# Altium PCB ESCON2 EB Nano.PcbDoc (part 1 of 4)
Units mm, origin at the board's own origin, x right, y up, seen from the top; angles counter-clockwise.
Board outline 67 x 70 mm, 6 copper layers (Top Side, Mid Layer 1, Mid Layer 2, Mid Layer 5, Mid Layer 6, Bottom Side), stack 1.48 mm thick; 293 components, 114 nets, 848 pads, 2005 vias.
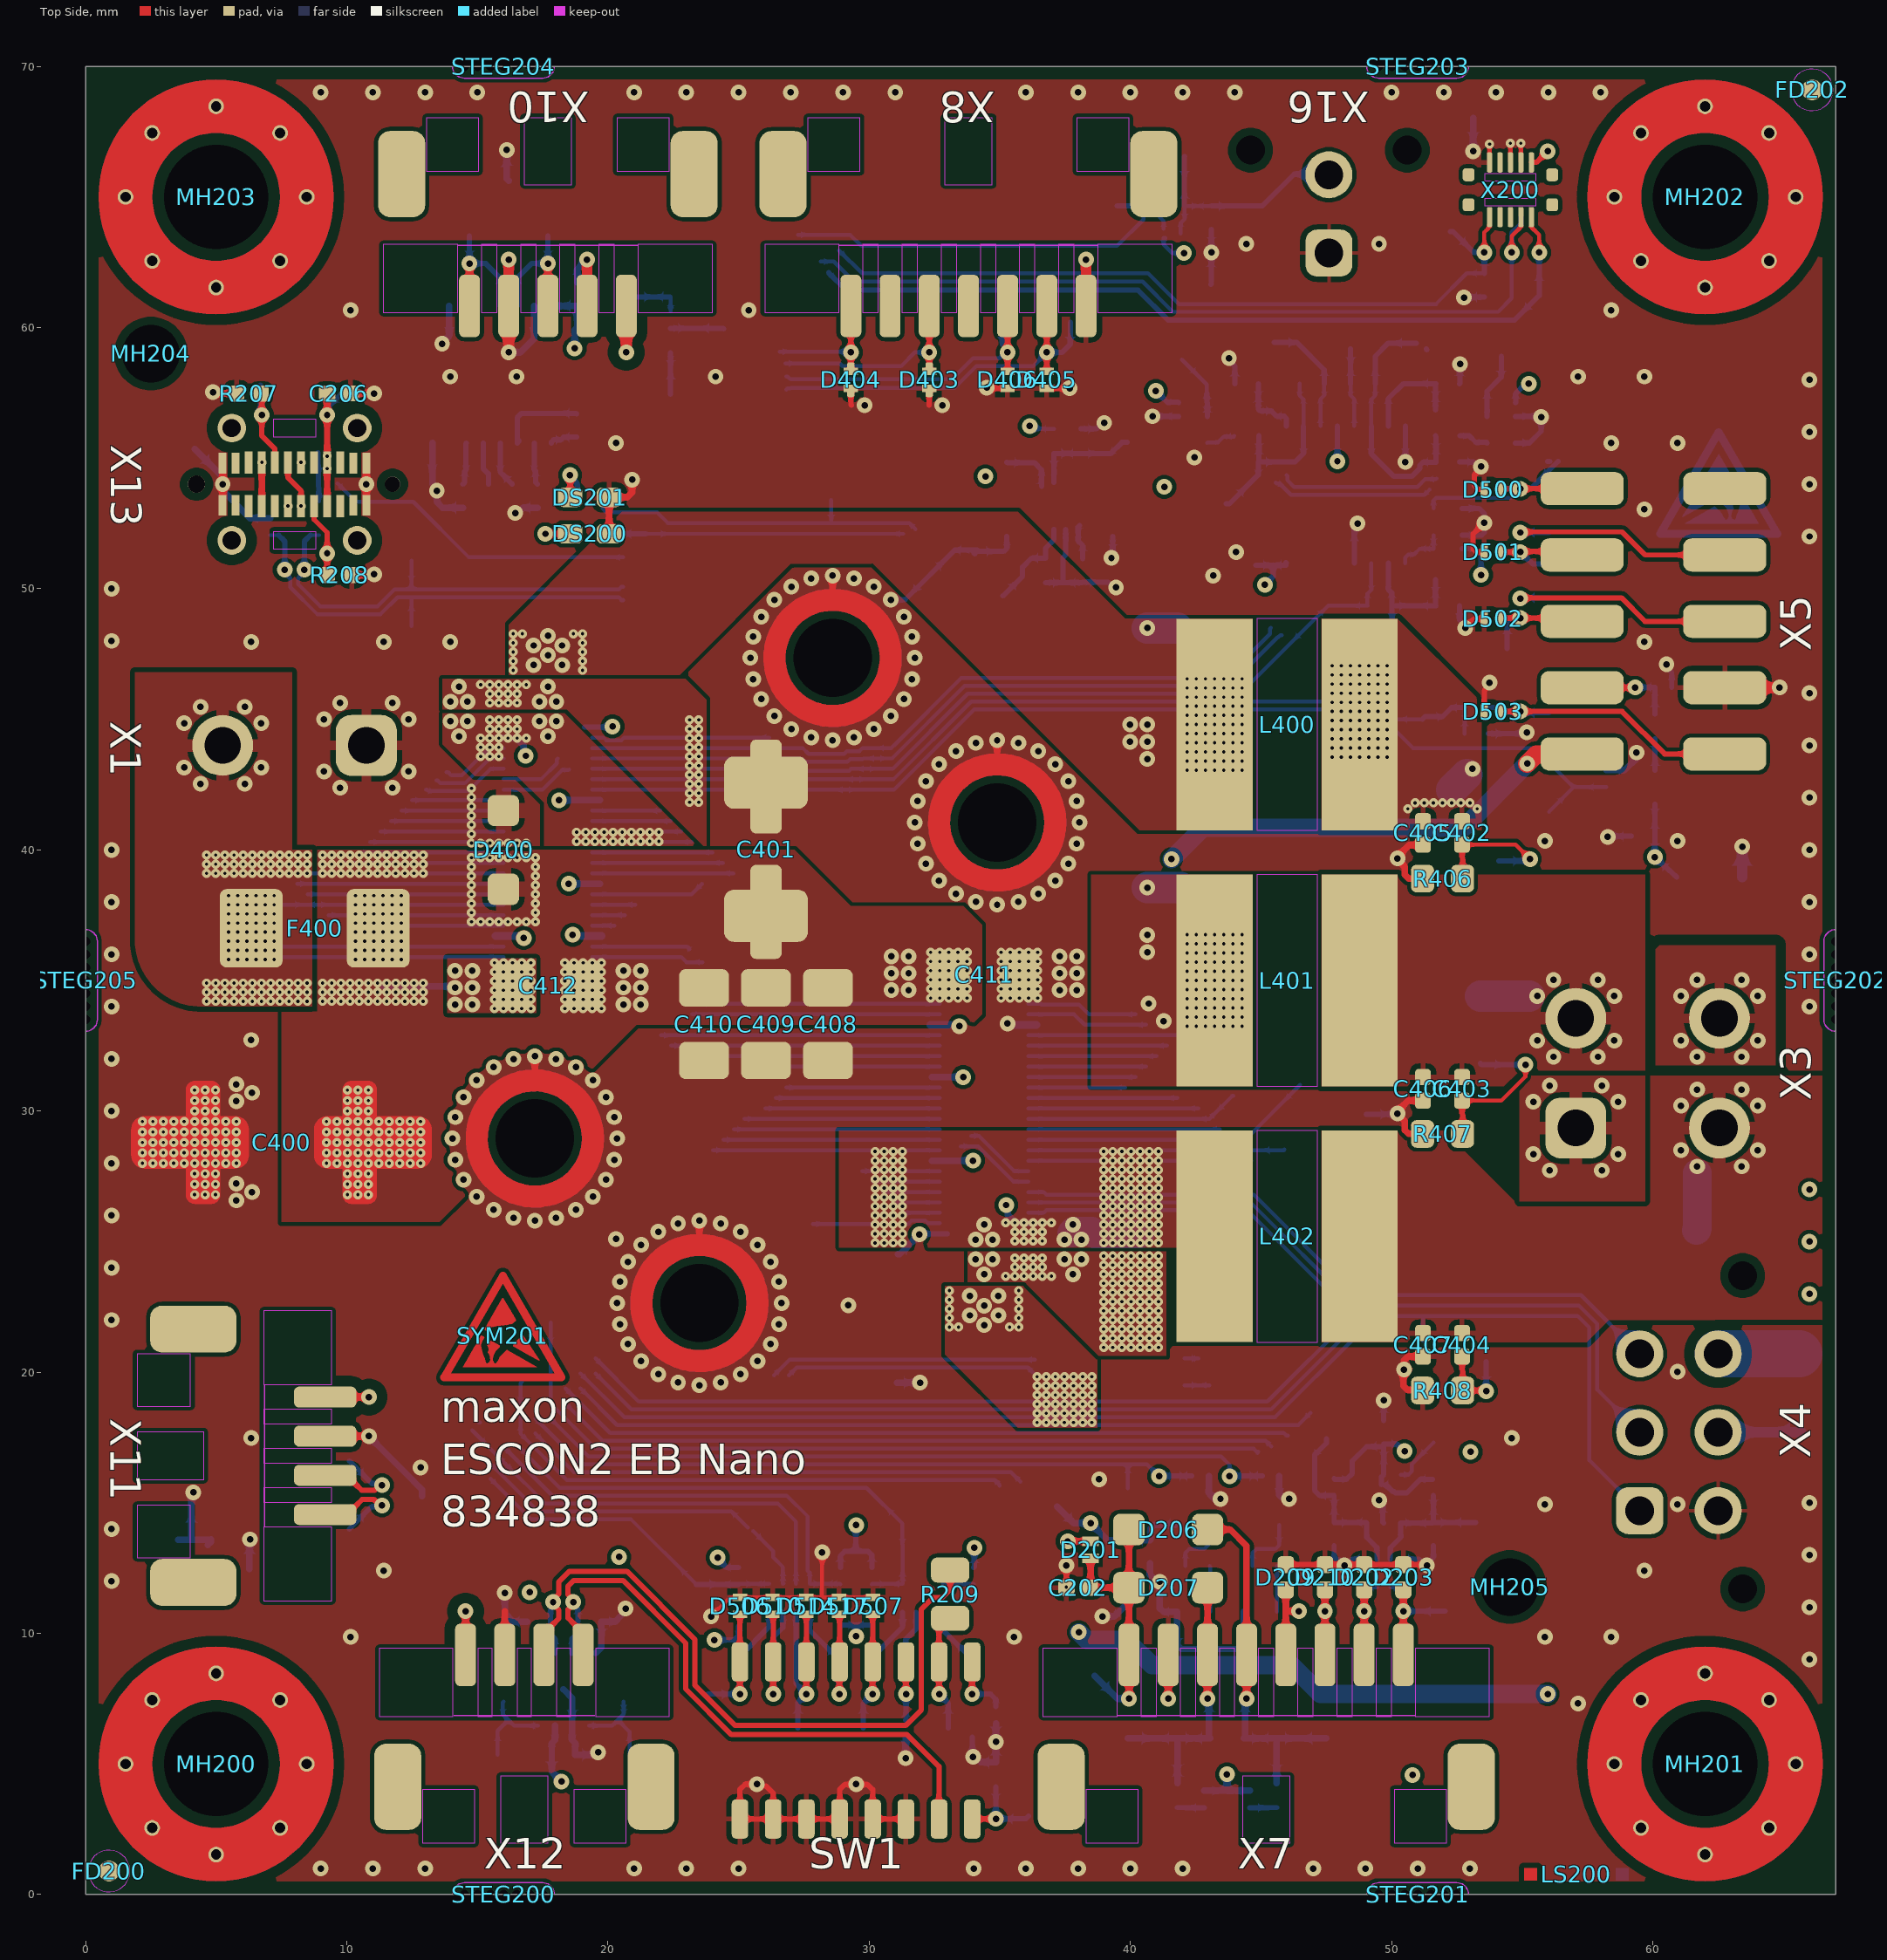
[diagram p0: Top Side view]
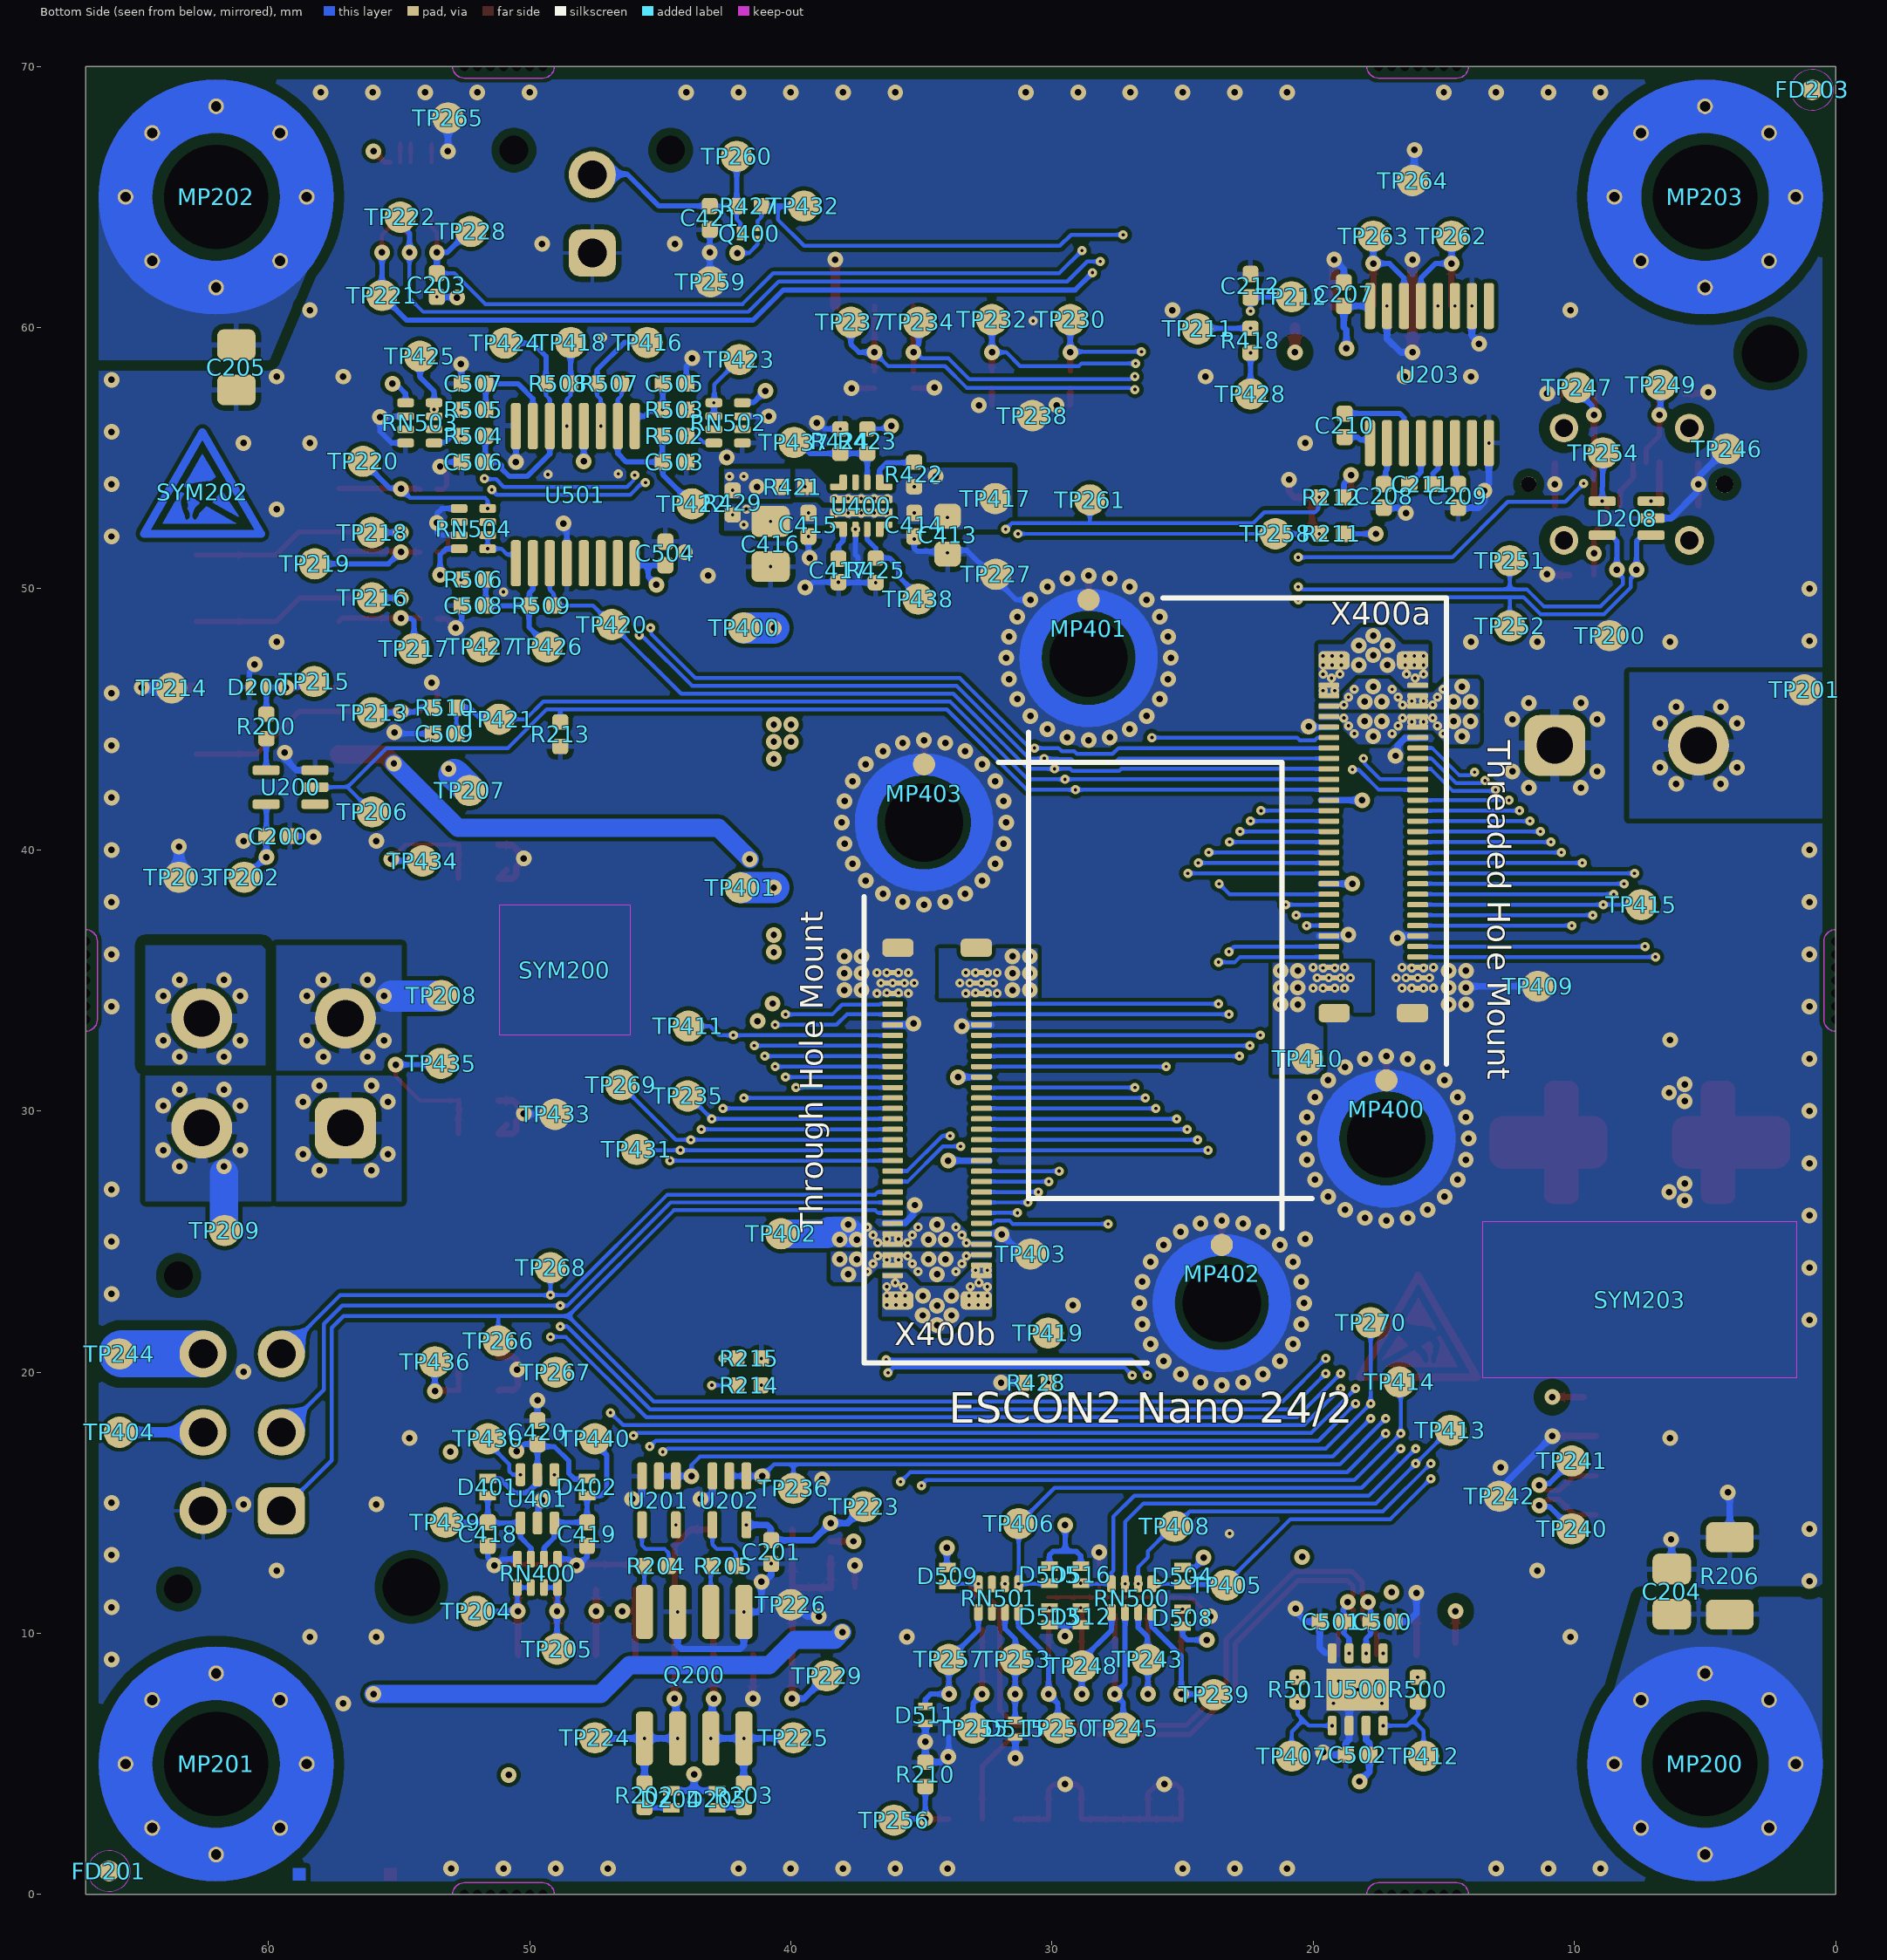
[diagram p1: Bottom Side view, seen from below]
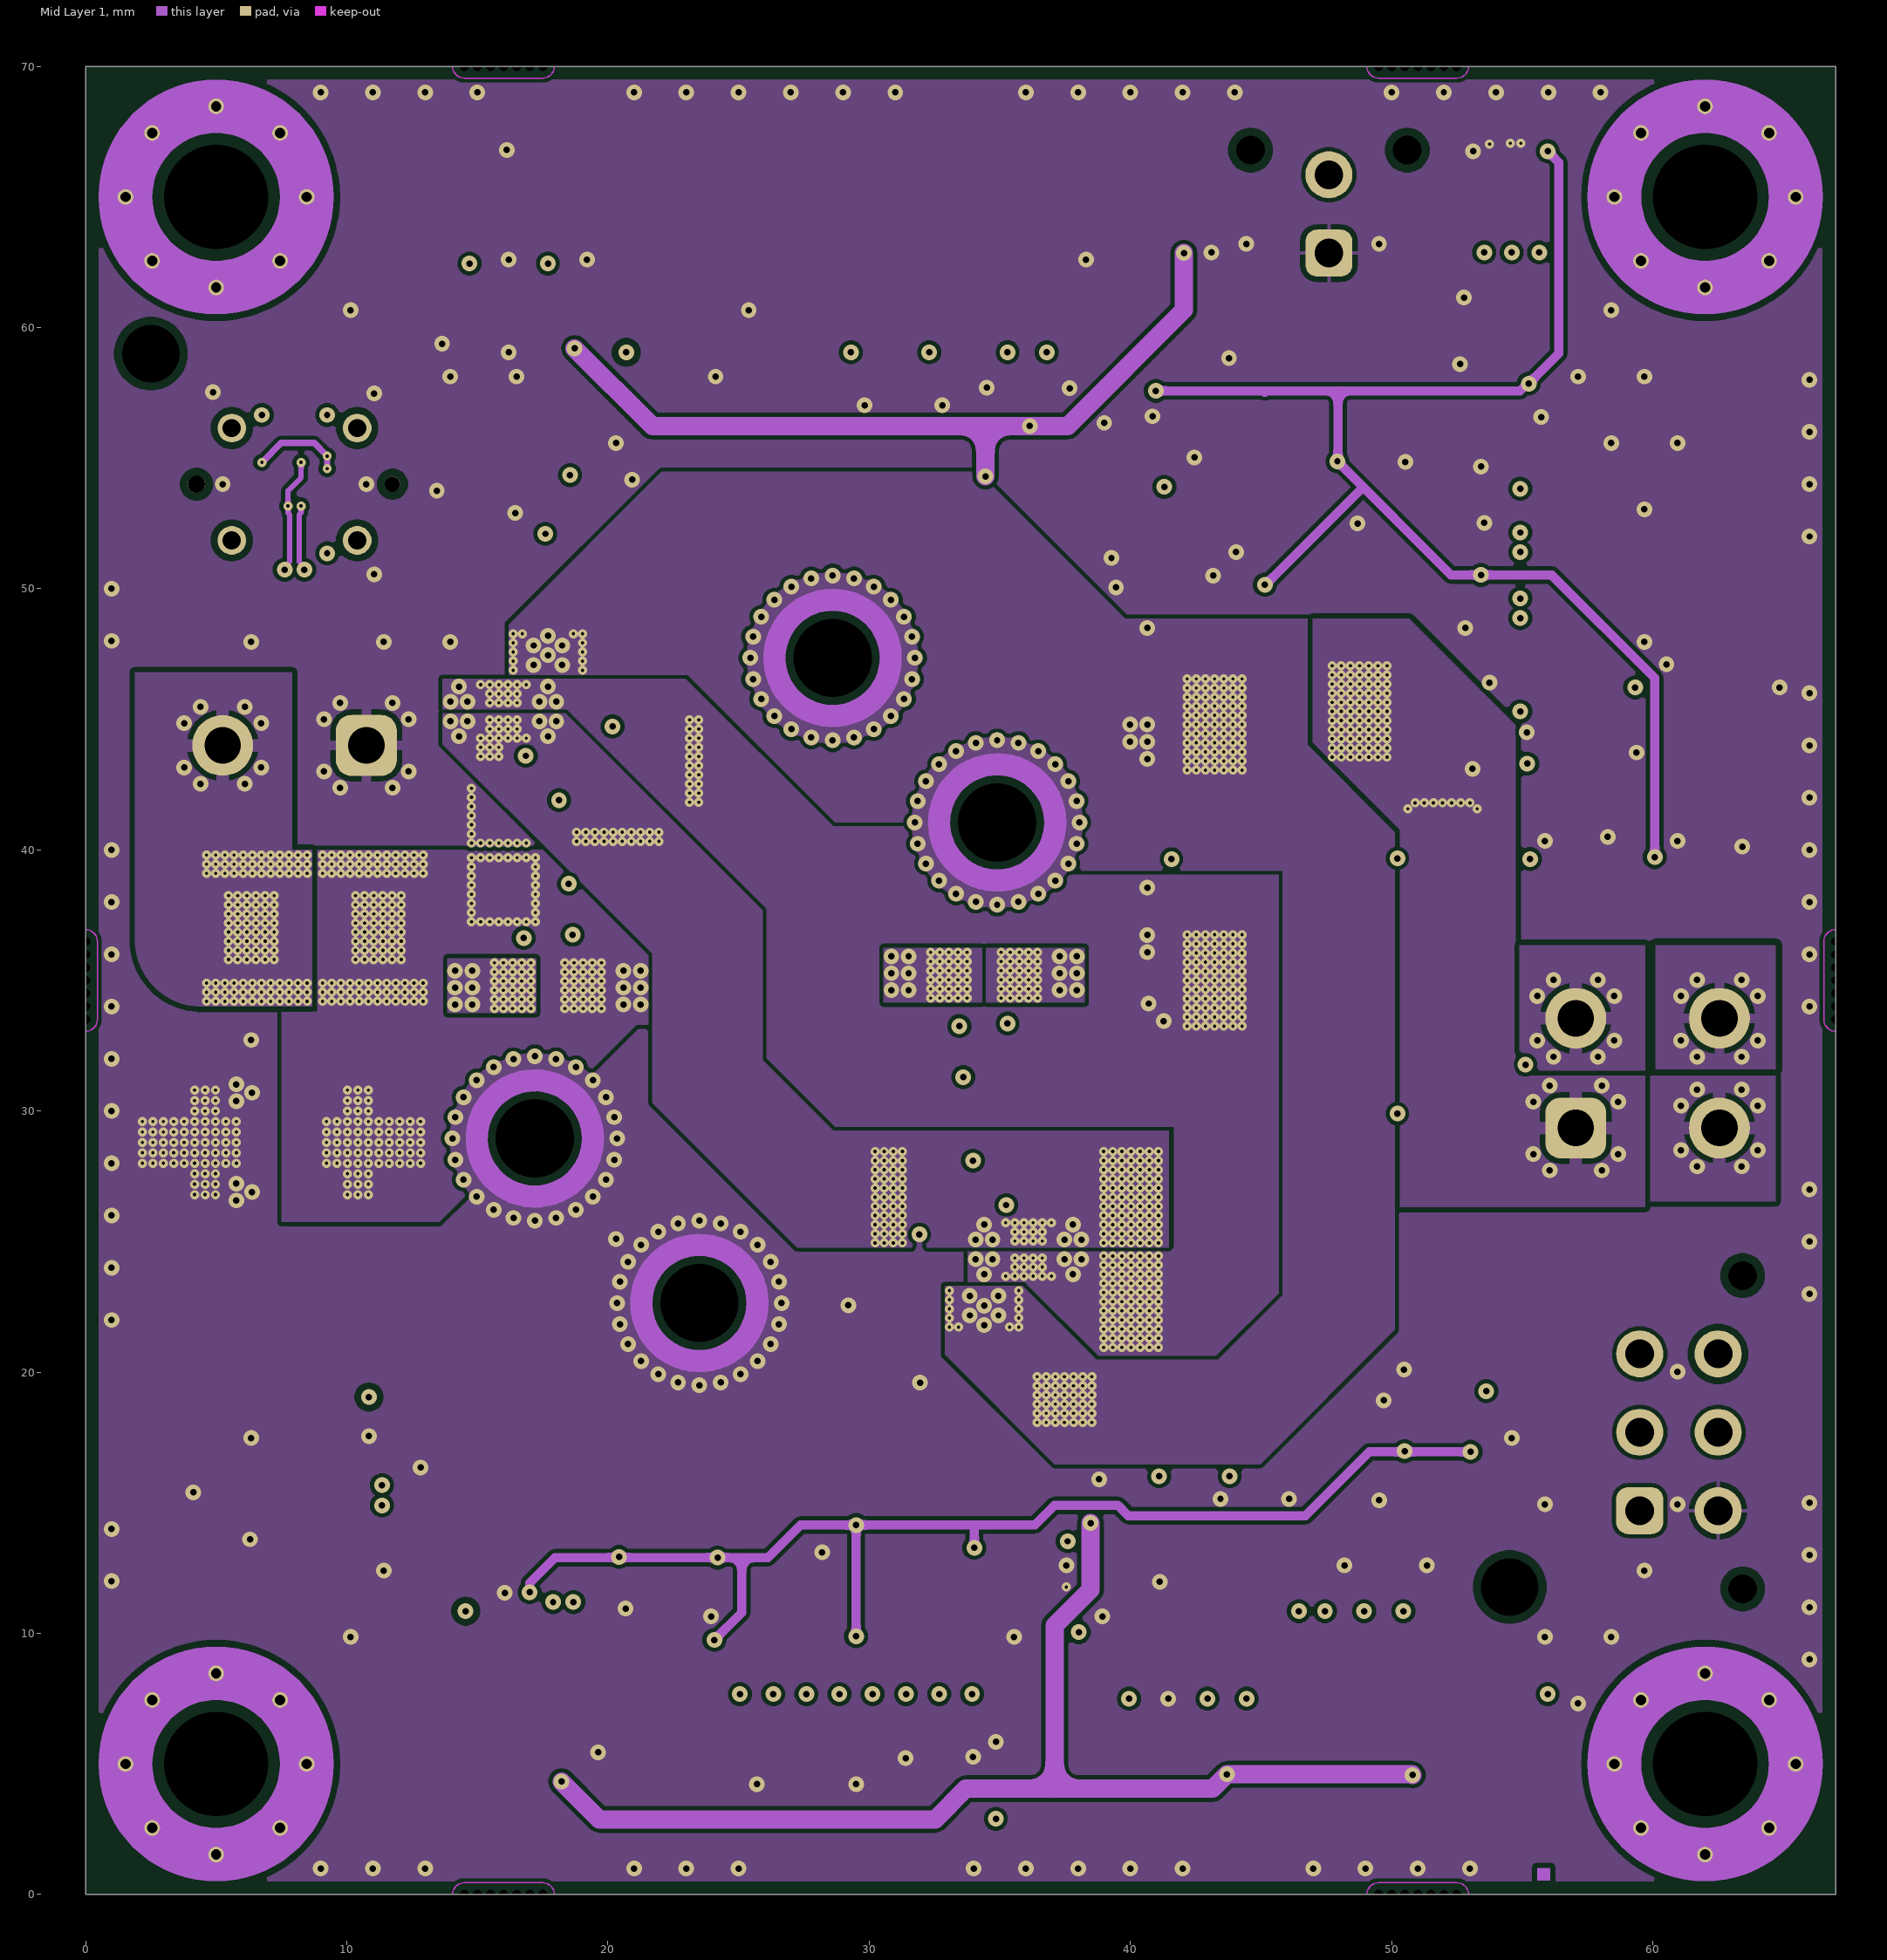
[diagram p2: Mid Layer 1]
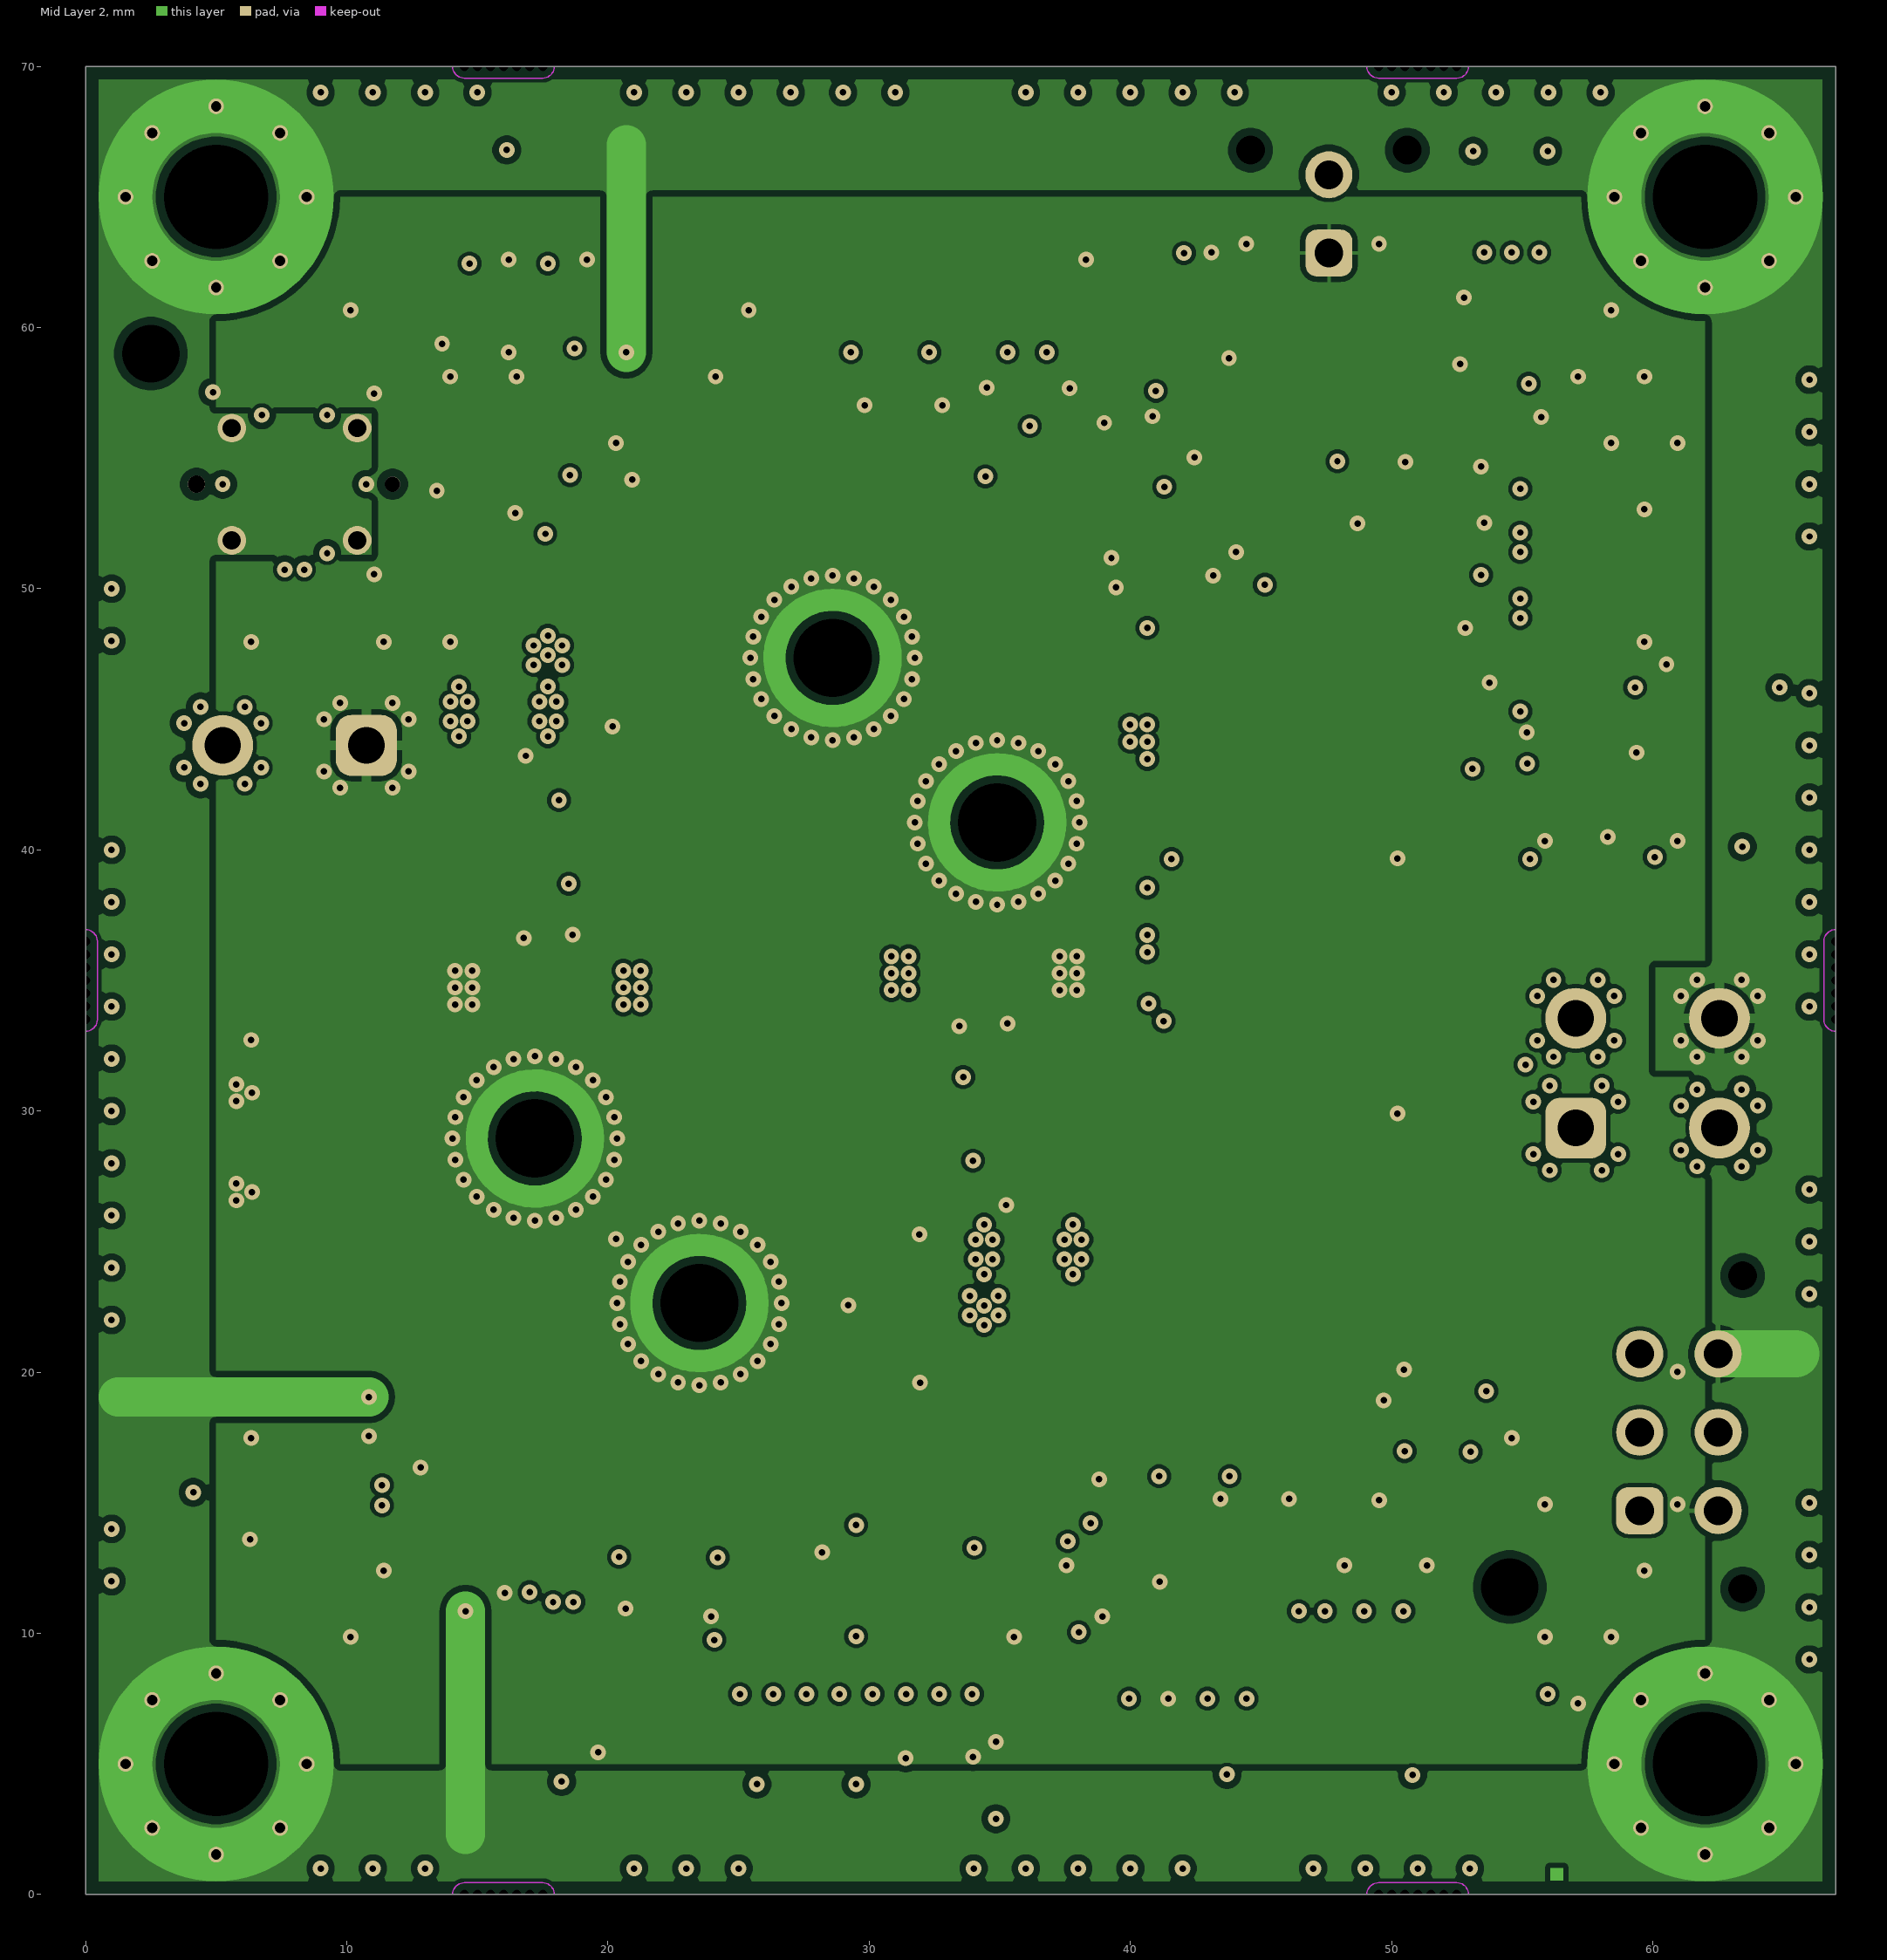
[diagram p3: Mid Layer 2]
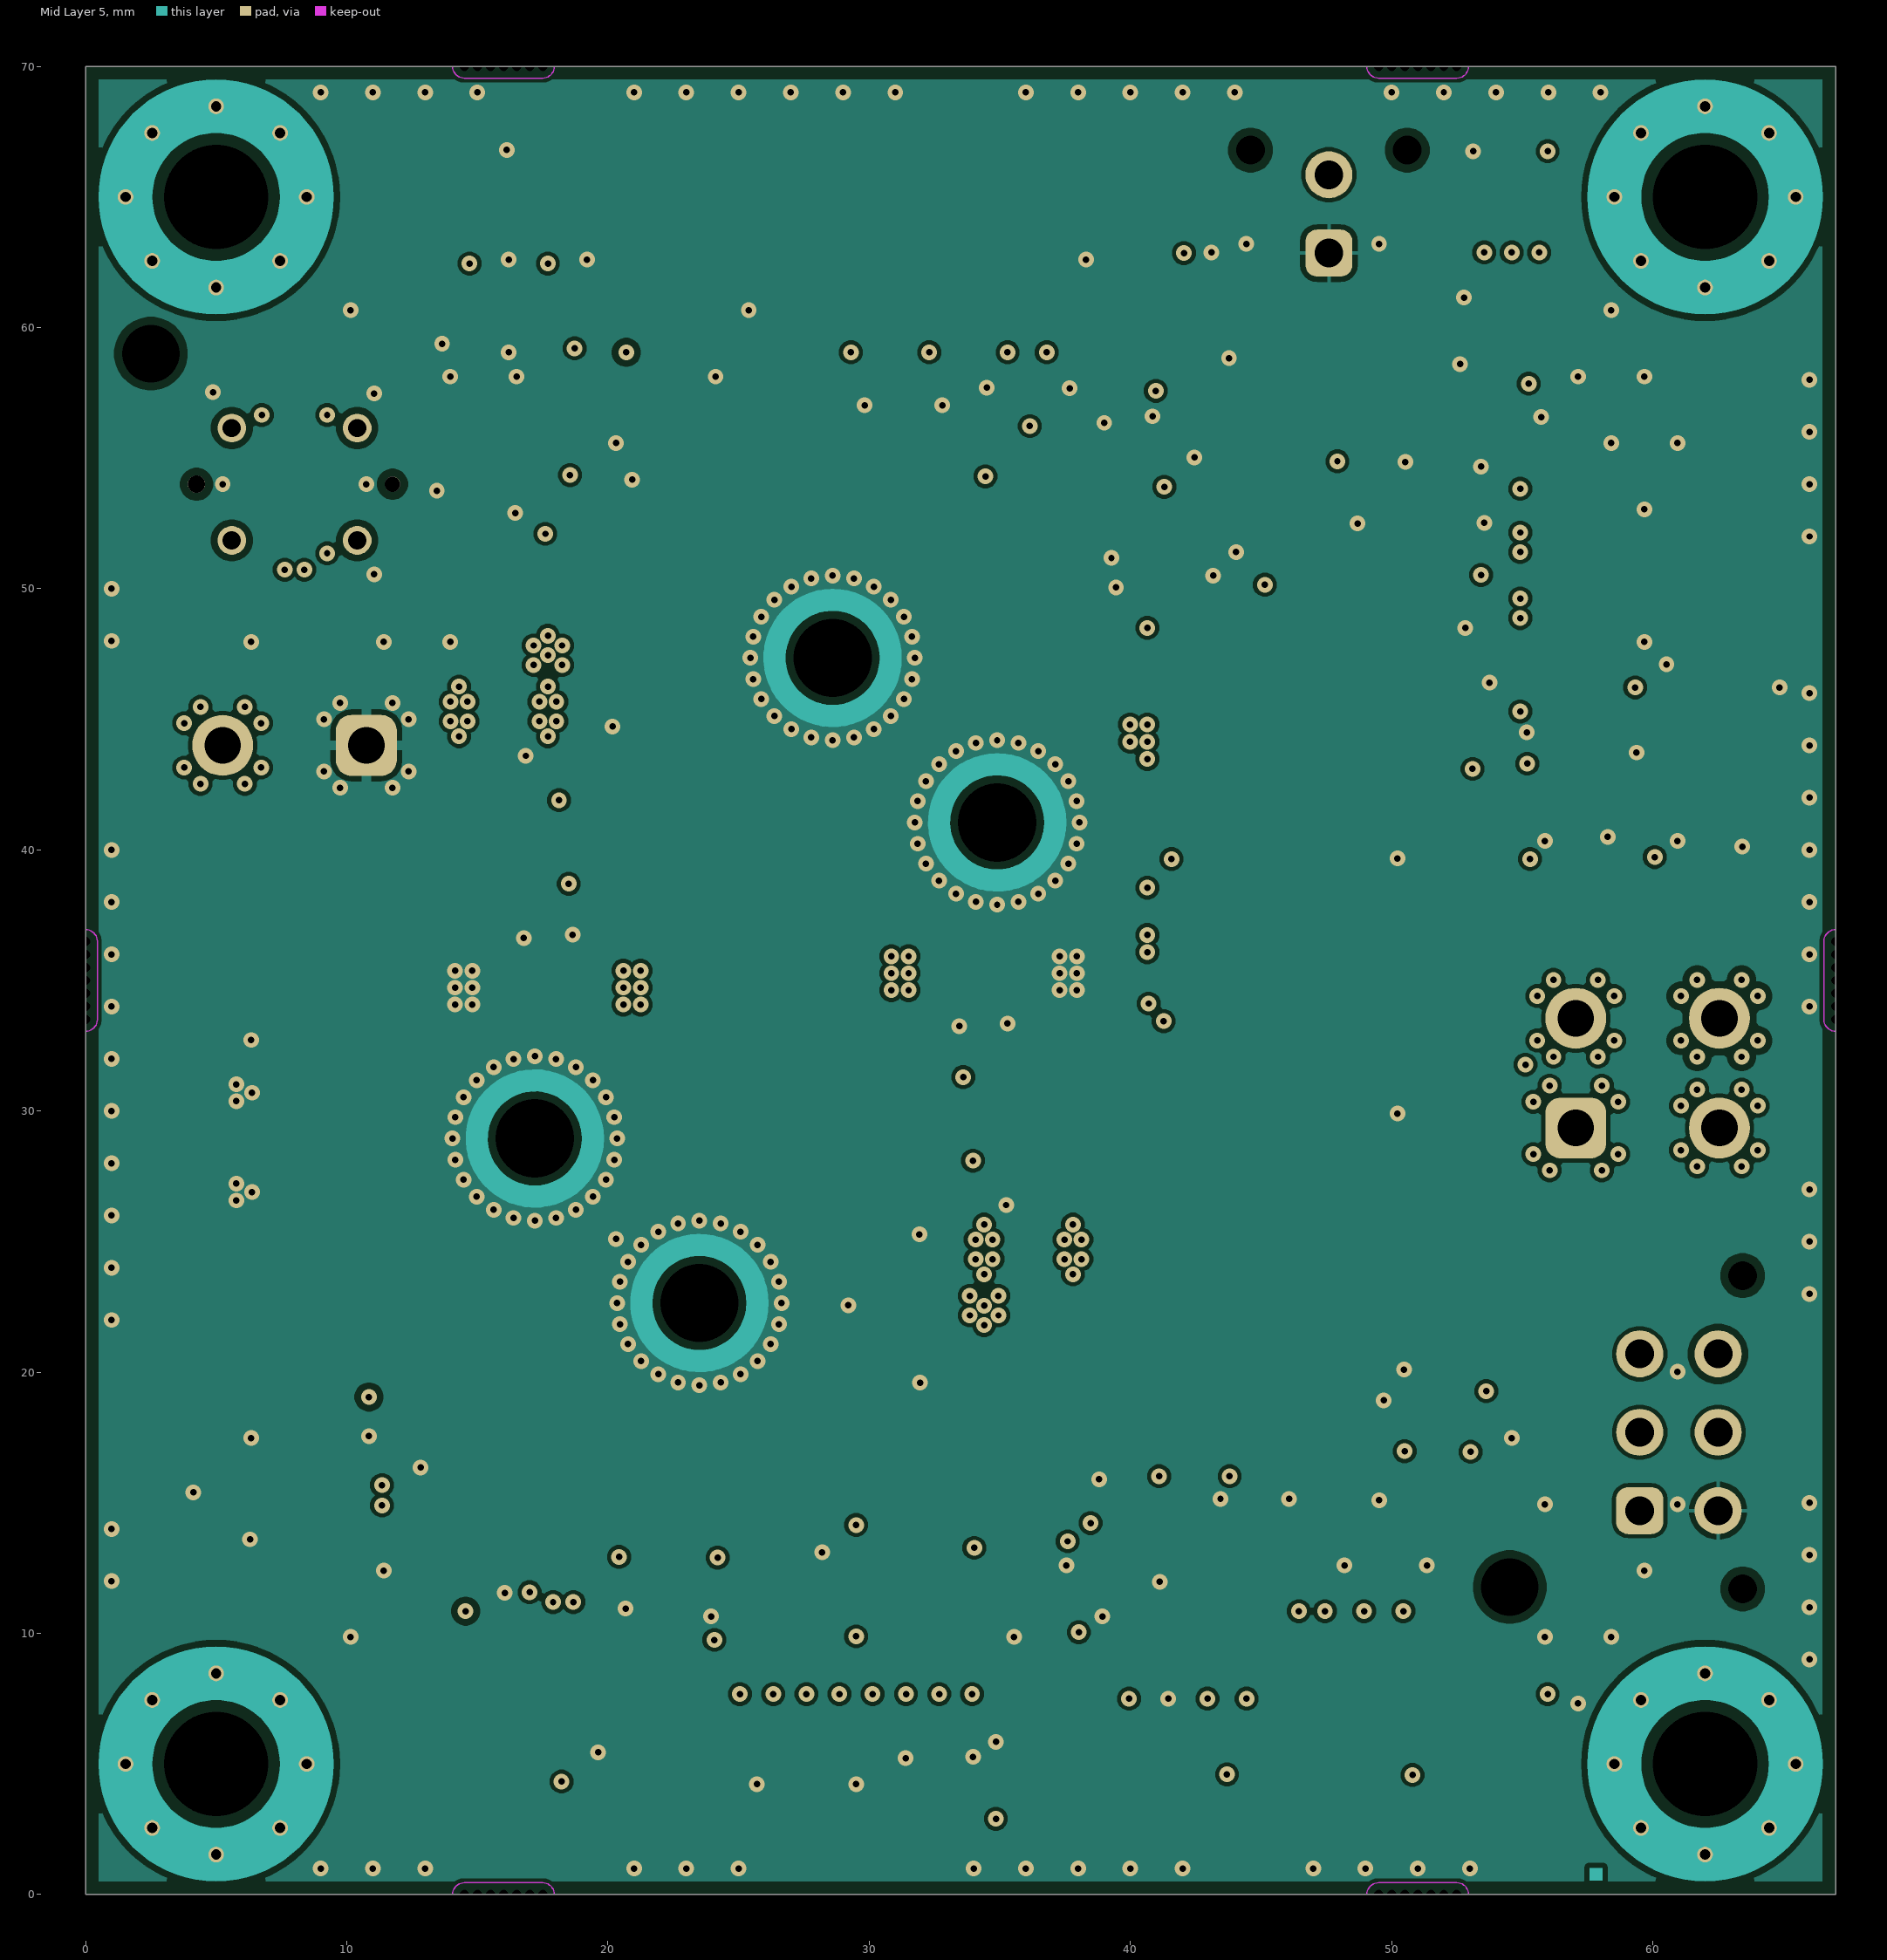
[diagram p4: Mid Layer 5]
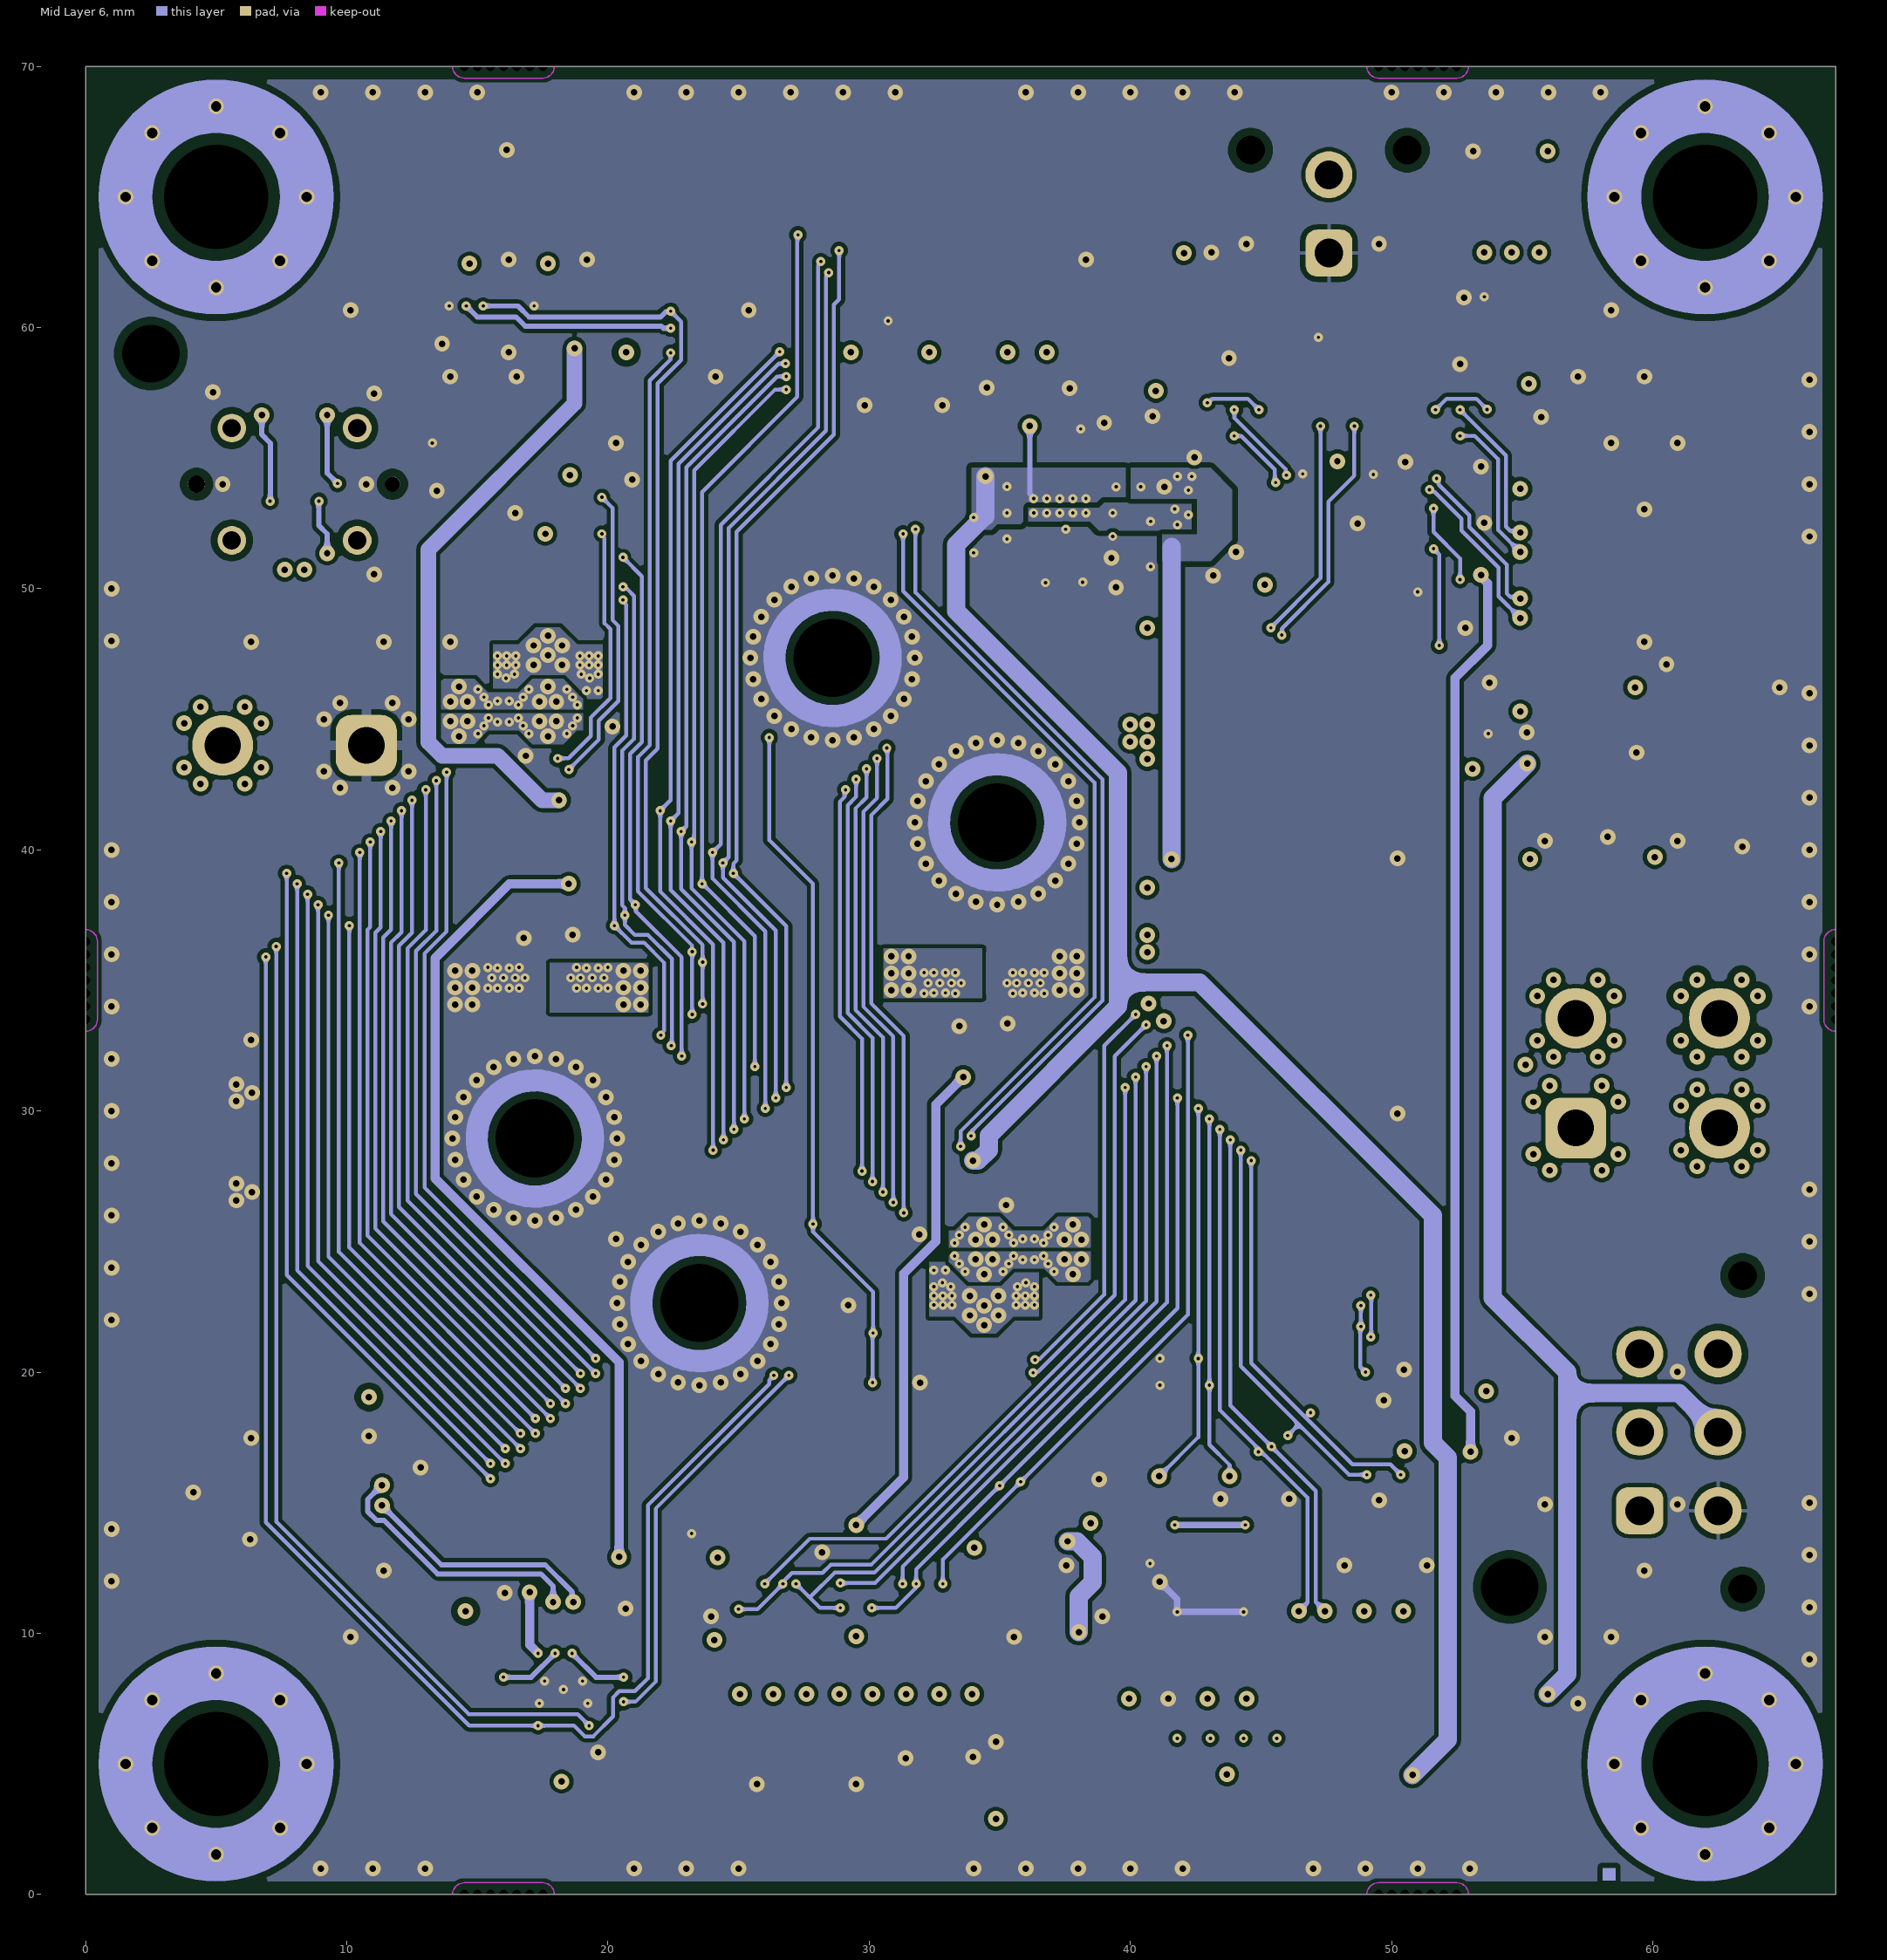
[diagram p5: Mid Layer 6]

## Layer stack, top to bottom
Top Solder: solder mask 0.015, Dk 3.5
Top Side: signal copper 0.03
Dielectric 1: prepreg 0.065, Dk 3.5
Mid Layer 1: signal copper 0.035
Core 1: core 0.51, Dk 5.1
Mid Layer 2: signal copper 0.035
Dielectric 2: prepreg 0.125, Dk 3.7
Mid Layer 5: signal copper 0.035
Core 3: core 0.51, Dk 5.1
Mid Layer 6: signal copper 0.035
Dielectric 4: prepreg 0.065, Dk 3.5
Bottom Side: signal copper 0.035
Bottom Solder: solder mask 0.015, Dk 3.5

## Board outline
0,0 0,70 67,70 67,0

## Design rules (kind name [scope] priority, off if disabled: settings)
AssemblyTestPointUsage [All] p1: valid=2
AssemblyTestpoint [All] p1: testpointundercomponent=TRUE minsize=1 maxsize=2 preferedsize=1 minholesize=0 maxholesize=0 preferedholesize=0 testpointgrid=0.05 usegrid=FALSE gridoriginx=120 gridoriginy=100 gridtolerance=0 allowsidebottom=TRUE minspacing=2.5 padholecenterclearance=0.6
BoardOutlineClearance BOC_Overlay [OnLayer('Top Designator') OR OnLayer('Bottom Designator')] p1: gap=0 ignorepadtopadclearanceinfootprint=FALSE
BoardOutlineClearance BOC_Text [isText] p2: gap=0 ignorepadtopadclearanceinfootprint=FALSE
BoardOutlineClearance BOC_Fiducials [InComponent('FD*')] p3: gap=0.1 ignorepadtopadclearanceinfootprint=FALSE
BoardOutlineClearance BOC_Steg [InComponent('STEG*')] p4: gap=0 ignorepadtopadclearanceinfootprint=FALSE
BoardOutlineClearance BOC_Keepout [IsKeepout] p5: gap=0 ignorepadtopadclearanceinfootprint=FALSE
BoardOutlineClearance BOC_All [All] p6: gap=0.5 ignorepadtopadclearanceinfootprint=FALSE
Clearance C_NPTHtoAll [(ObjectKind = 'Pad') AND (Layer = 'MultiLayer') AND (PadIsPlated = 'False') AND NOT HasFootprint('Steg*')] p1: gap=0.3 ignorepadtopadclearanceinfootprint=FALSE
Clearance C_LStoAll [InComponent('LS*')] p2: gap=0.2 ignorepadtopadclearanceinfootprint=FALSE
Clearance C_NetSGNDtoAll_onOutside [InNet('SGND') AND ( ExistsOnLayer('Top Side') OR ExistsOnLayer('Bottom Side') ) vs ExistsOnLayer('Top Side') OR ExistsOnLayer('Bottom Side')] p3: gap=0.4 ignorepadtopadclearanceinfootprint=FALSE
Clearance C_NetSGNDtoAll_onMid [InNet('SGND') AND ( ExistsOnLayer('Mid Layer 1') OR ExistsOnLayer('Mid Layer 2') OR ExistsOnLayer('Mid Layer 3') OR ExistsOnLayer('Mid Layer 4') OR ExistsOnLayer('Mid Layer 5') OR ExistsOnLayer('Mid Layer 6') OR ExistsOnLayer('Mid Layer 7') OR ExistsOnLayer('Mid Layer 8') OR ExistsOnLayer('Mid Layer 9') OR ExistsOnLayer('Mid Layer 10') ) vs ExistsOnLayer('Mid Layer 1') OR ExistsOnLayer('Mid Layer 2') OR ExistsOnLayer('Mid Layer 3') OR ExistsOnLayer('Mid Layer 4') OR ExistsOnLayer('Mid Layer 5') OR ExistsOnLayer('Mid Layer 6') OR ExistsOnLayer('Mid Layer 7') OR ExistsOnLayer('Mid Layer 8') OR ExistsOnLayer('Mid Layer 9') OR ExistsOnLayer('Mid Layer 10')] p4: gap=0.25 ignorepadtopadclearanceinfootprint=FALSE except(0.3: Arc-Hole Track-Hole SMDPad-Hole THPad-Hole Via-Hole Fill-Hole Poly-Hole Region-Hole Text-Hole)
Clearance C_ClassHVtoPolygon [InPolygon and InNetClass('HV') vs InPolygon] p5: gap=0.2 ignorepadtopadclearanceinfootprint=FALSE
Clearance C_ClassNVtoPolygon [InPolygon and InNetClass('NV') vs InPolygon] p6: gap=0.15 ignorepadtopadclearanceinfootprint=FALSE
Clearance C_PolygonPolygon [InPolygon vs InPolygon] p7: gap=0.2 ignorepadtopadclearanceinfootprint=FALSE
Clearance C_ClassHVtoAll_onOutside [InNetClass('HV') AND (ExistsOnLayer('Top Side') OR ExistsOnLayer('Bottom Side')) vs ExistsOnLayer('Top Side') OR ExistsOnLayer('Bottom Side')] p8: gap=0.15 ignorepadtopadclearanceinfootprint=FALSE
Clearance C_ClassHVtoAll_onMid [InNetClass('HV')  AND ( ExistsOnLayer('Mid Layer 1') OR ExistsOnLayer('Mid Layer 2') OR ExistsOnLayer('Mid Layer 3') OR ExistsOnLayer('Mid Layer 4') OR ExistsOnLayer('Mid Layer 5') OR ExistsOnLayer('Mid Layer 6') OR ExistsOnLayer('Mid Layer 7') OR ExistsOnLayer('Mid Layer 8') OR ExistsOnLayer('Mid Layer 9') OR ExistsOnLayer('Mid Layer 10') ) vs ExistsOnLayer('Mid Layer 1') OR ExistsOnLayer('Mid Layer 2') OR ExistsOnLayer('Mid Layer 3') OR ExistsOnLayer('Mid Layer 4') OR ExistsOnLayer('Mid Layer 5') OR ExistsOnLayer('Mid Layer 6') OR ExistsOnLayer('Mid Layer 7') OR ExistsOnLayer('Mid Layer 8') OR ExistsOnLayer('Mid Layer 9') OR ExistsOnLayer('Mid Layer 10')] p9: gap=0.15 ignorepadtopadclearanceinfootprint=FALSE
Clearance C_ClassNVtoAll_onOutside [InNetClass('NV') AND (ExistsOnLayer('Top Side') OR ExistsOnLayer('Bottom Side')) vs ExistsOnLayer('Top Side') OR ExistsOnLayer('Bottom Side')] p10: gap=0.15 ignorepadtopadclearanceinfootprint=FALSE
Clearance C_ClassNVtoAll_onMid [InNetClass('NV')  AND ( ExistsOnLayer('Mid Layer 1') OR ExistsOnLayer('Mid Layer 2') OR ExistsOnLayer('Mid Layer 3') OR ExistsOnLayer('Mid Layer 4') OR ExistsOnLayer('Mid Layer 5') OR ExistsOnLayer('Mid Layer 6') OR ExistsOnLayer('Mid Layer 7') OR ExistsOnLayer('Mid Layer 8') OR ExistsOnLayer('Mid Layer 9') OR ExistsOnLayer('Mid Layer 10') ) vs ExistsOnLayer('Mid Layer 1') OR ExistsOnLayer('Mid Layer 2') OR ExistsOnLayer('Mid Layer 3') OR ExistsOnLayer('Mid Layer 4') OR ExistsOnLayer('Mid Layer 5') OR ExistsOnLayer('Mid Layer 6') OR ExistsOnLayer('Mid Layer 7') OR ExistsOnLayer('Mid Layer 8') OR ExistsOnLayer('Mid Layer 9') OR ExistsOnLayer('Mid Layer 10')] p11: gap=0.15 ignorepadtopadclearanceinfootprint=FALSE
Clearance C_NoClasstoAll_onOutside [(ExistsOnLayer('Top Side') OR ExistsOnLayer('Bottom Side')) vs ExistsOnLayer('Top Side') OR ExistsOnLayer('Bottom Side')] p12: gap=0.15 ignorepadtopadclearanceinfootprint=FALSE except(0.149: Via-Fill Via-Poly Via-Region)
Clearance C_NoClasstoAll_onMid [( ExistsOnLayer('Mid Layer 1') OR ExistsOnLayer('Mid Layer 2') OR ExistsOnLayer('Mid Layer 3') OR ExistsOnLayer('Mid Layer 4') OR ExistsOnLayer('Mid Layer 5') OR ExistsOnLayer('Mid Layer 6') OR ExistsOnLayer('Mid Layer 7') OR ExistsOnLayer('Mid Layer 8') OR ExistsOnLayer('Mid Layer 9') OR ExistsOnLayer('Mid Layer 10') ) vs ExistsOnLayer('Mid Layer 1') OR ExistsOnLayer('Mid Layer 2') OR ExistsOnLayer('Mid Layer 3') OR ExistsOnLayer('Mid Layer 4') OR ExistsOnLayer('Mid Layer 5') OR ExistsOnLayer('Mid Layer 6') OR ExistsOnLayer('Mid Layer 7') OR ExistsOnLayer('Mid Layer 8') OR ExistsOnLayer('Mid Layer 9') OR ExistsOnLayer('Mid Layer 10')] p13: gap=0.15 ignorepadtopadclearanceinfootprint=FALSE
Clearance C_STEGKeepout [InComponent('STEG*') vs IsKeepout] p14: gap=0 ignorepadtopadclearanceinfootprint=FALSE
Clearance C_All [All] p15: gap=0.15 ignorepadtopadclearanceinfootprint=FALSE except(0: SMDPad-Hole THPad-Hole Via-Hole Fill-Hole Poly-Hole Region-Hole Text-Hole; 0.3: Arc-Hole Track-Hole)
ComponentClearance CC_TPMToTP [InComponent('TPM*') vs InComponent('TP*')] p1: gap=0 collisioncheckmode=3 verticalgap=0 showdistances=FALSE
ComponentClearance CC_BarcodeToAll [(ObjectKind = '3D Body') And (Identifier = 'Barcode')] p2: gap=0 collisioncheckmode=3 verticalgap=0 showdistances=FALSE donotcheckwithout3dbody=TRUE checkcomponentboundary=TRUE
ComponentClearance CC_Free3DBody [(ObjectKind = '3D Body') and not InComponent('*') vs (ObjectKind = '3D Body') and not InComponent('*')] p3: gap=0 collisioncheckmode=3 verticalgap=0 showdistances=FALSE
ComponentClearance CC_CMP8MMtoTP [InComponent('*')  and (AsMM(Height) >= 8.0) vs InComponent('TP*')] p4 off: gap=4 collisioncheckmode=3 verticalgap=4 showdistances=FALSE donotcheckwithout3dbody=TRUE checkcomponentboundary=TRUE
ComponentClearance CC_CMPtoTP [InComponent('*') vs InComponent('TP*')] p5: gap=0.5 collisioncheckmode=3 verticalgap=0.5 showdistances=FALSE donotcheckwithout3dbody=TRUE checkcomponentboundary=TRUE
ComponentClearance CC_AllToAll [All] p6: gap=0 collisioncheckmode=3 verticalgap=0 showdistances=FALSE checkcomponentboundary=TRUE
DiffPairsRouting DPR_All [All] p1: maxlimit=0.3 minlimit=0.2 mostfreqgap=0.2 toplayer_minwidth=0.2 toplayer_maxwidth=0.25 toplayer_prefwidth=0.2 midlayer1_minwidth=0.2 midlayer1_maxwidth=0.25 midlayer1_prefwidth=0.2 midlayer2_minwidth=0.2 midlayer2_maxwidth=0.25 midlayer2_prefwidth=0.2 midlayer4_minwidth=0.2 midlayer4_maxwidth=0.25 midlayer4_prefwidth=0.2 midlayer6_minwidth=0.2 midlayer6_maxwidth=0.25 midlayer6_prefwidth=0.2 bottomlayer_minwidth=0.2 bottomlayer_maxwidth=0.25 bottomlayer_prefwidth=0.2 maxuncoupledlength=12.7
FabricationTestPointUsage [All] p1: valid=2 allowmultiple=FALSE
FabricationTestpoint [All] p1: side=3 testpointundercomponent=TRUE minsize=0.1 maxsize=10 preferedsize=1 minholesize=0 maxholesize=10 preferedholesize=1 testpointgrid=0.025 allowsidetop=TRUE allowsidebottom=TRUE usegrid=FALSE gridtolerance=0
HoleSize HS_All [All] p1: absolutevalues=TRUE maxlimit=5 minlimit=0.125 maxpercent=80.000 minpercent=20.000
HoleToHoleClearance HtHC_MicroToMicro [IsMicroVia vs IsMicroVia] p1: gap=0.2 allowstackedmicrovias=TRUE
HoleToHoleClearance HtHC_MicroToBuried [IsMicroVia vs isBuriedVia] p2: gap=0.225 allowstackedmicrovias=FALSE
HoleToHoleClearance HtHC_ThruToBuried [IsThruVia vs isBuriedVia] p3: gap=0.4 allowstackedmicrovias=TRUE
HoleToHoleClearance HtHC_STEG [InComponent('STEG*') vs InComponent('STEG*')] p4: gap=0.1 allowstackedmicrovias=TRUE
HoleToHoleClearance HtHC_All [All] p5: gap=0.4 allowstackedmicrovias=TRUE
LayerPairs LP_All [All] p1: enforce=TRUE
MinimumSolderMaskSliver MSMS_All [All] p1: minsoldermaskwidth=0.1
NetAntennae NA_All [All] p1: netantennaetolerance=0
PasteMaskExpansion PME_All [All] p1: expansion=0
PolygonConnect PCS_Testpoint [Testpoint] p1: connectstyle=Direct reliefconductorwidth=0.254 reliefentries=4 polygonreliefangle="90 Angle" airgapwidth=0.254
PolygonConnect PCS_MountingHole [(InComponent('MH*'))] p2: connectstyle=Direct reliefconductorwidth=0.254 reliefentries=4 polygonreliefangle="90 Angle" airgapwidth=0.254
PolygonConnect PCS_MountingSpacer [(InComponent('MP*'))] p3: connectstyle=Direct reliefconductorwidth=0.254 reliefentries=4 polygonreliefangle="90 Angle" airgapwidth=0.254
PolygonConnect PCS_X400 [InComponent('X400a') or InComponent('X400b')] p4: connectstyle=Direct reliefconductorwidth=0.2 reliefentries=4 polygonreliefangle="90 Angle" airgapwidth=0.2
PolygonConnect PCS_D400 [InComponent('D400')] p5: connectstyle=Relief reliefconductorwidth=0.6 reliefentries=4 polygonreliefangle="90 Angle" airgapwidth=0.2
PolygonConnect PCS_L400-L402 [HasFootprint('INDDFN2_800X800X420L232X630N')] p6: connectstyle=Direct reliefconductorwidth=0.2 reliefentries=4 polygonreliefangle="90 Angle" airgapwidth=0.2
PolygonConnect PCS_X1_GND [InComponent('X1') vs InNet('GND')] p7: connectstyle=Relief reliefconductorwidth=0.375 reliefentries=4 polygonreliefangle="90 Angle" airgapwidth=0.2
PolygonConnect PCS_X1 [InComponent('X1')] p8: connectstyle=Relief reliefconductorwidth=0.5 reliefentries=4 polygonreliefangle="90 Angle" airgapwidth=0.2
PolygonConnect PCS_X16_GND [InComponent('X16') vs InNet('GND')] p9: connectstyle=Relief reliefconductorwidth=0.15 reliefentries=4 polygonreliefangle="90 Angle" airgapwidth=0.2
PolygonConnect PCS_X4_GND [InComponent('X4') vs InNet('GND')] p10: connectstyle=Relief reliefconductorwidth=0.15 reliefentries=4 polygonreliefangle="90 Angle" airgapwidth=0.2
PolygonConnect PCS_X4 [InComponent('X16')] p11: connectstyle=Relief reliefconductorwidth=0.15 reliefentries=4 polygonreliefangle="90 Angle" airgapwidth=0.2
PolygonConnect PCS_X3_SGND [InComponent('X3') vs InNet('SGND')] p12: connectstyle=Relief reliefconductorwidth=0.375 reliefentries=4 polygonreliefangle="90 Angle" airgapwidth=0.2
PolygonConnect PCS_X3 [InComponent('X3')] p13: connectstyle=Relief reliefconductorwidth=0.5 reliefentries=4 polygonreliefangle="90 Angle" airgapwidth=0.2
PolygonConnect PCS_ELKOs [InComponent('C400') or InComponent('C401') or InComponent('C408') or InComponent('C409') or InComponent('C410') or InComponent('C411') or InComponent('C412')] p14: connectstyle=Direct reliefconductorwidth=0.6 reliefentries=4 polygonreliefangle="90 Angle" airgapwidth=0.2
PolygonConnect PCS_SODFL [HasFootprint('SODFL359X170X143L65X95N')] p15: connectstyle=Relief reliefconductorwidth=0.6 reliefentries=4 polygonreliefangle="90 Angle" airgapwidth=0.2
PolygonConnect PCS_Fuse [HasFootprint('FUSC650X370X403L148N')] p16: connectstyle=Direct reliefconductorwidth=0.6 reliefentries=4 polygonreliefangle="90 Angle" airgapwidth=0.2
PolygonConnect PCS_X13 [HasFootprint('GTC_USB4115-03-C')] p17: connectstyle=Direct reliefconductorwidth=0.6 reliefentries=4 polygonreliefangle="90 Angle" airgapwidth=0.2
PolygonConnect PCS_5V0 [InComponent('U400') or InComponent('C413') or InComponent('C414') or InComponent('R421') or InComponent('R422') or InComponent('C415') or InComponent('C416') or InComponent('R429') vs InNet('5V0') or InNet('5V0_sensor1_2') or InNet('NetC415_2')] p18: connectstyle=Direct reliefconductorwidth=0.254 reliefentries=4 polygonreliefangle="90 Angle" airgapwidth=0.254
PolygonConnect PCS_U500 [InComponent('U500')] p19: connectstyle=Direct reliefconductorwidth=0.254 reliefentries=4 polygonreliefangle="90 Angle" airgapwidth=0.254
PolygonConnect PCS_DefaultComponents [InComponent('*')] p20: connectstyle=Relief reliefconductorwidth=0.2 reliefentries=4 polygonreliefangle="90 Angle" airgapwidth=0.2
PolygonConnect PCS_All [All] p21: connectstyle=Direct reliefconductorwidth=0.254 reliefentries=4 polygonreliefangle="90 Angle" airgapwidth=0.254
RoutingLayers RL_All [All] p1: top layer_v5=TRUE mid layer 1_v5=TRUE mid layer 2_v5=TRUE mid layer 4_v5=TRUE mid layer 6_v5=TRUE bottom layer_v5=TRUE
RoutingTopology RT_All [All] p1: topology=Shortest
RoutingVias RVS_MicroVia [IsMicroVia] p1: holewidth=0.125 width=0.35 viastyle="Through Hole" minholewidth=0.125 minwidth=0.35 maxholewidth=0.125 maxwidth=0.35
RoutingVias RVS_SkipVia [IsSkipVia] p2: holewidth=2 width=2 viastyle="Through Hole" minholewidth=2 minwidth=2 maxholewidth=2 maxwidth=2
RoutingVias RVS_BlindVia [IsBlindVia] p3: holewidth=2 width=2 viastyle="Through Hole" minholewidth=2 minwidth=2 maxholewidth=2 maxwidth=2
RoutingVias RVS_BuriedVia [IsBuriedVia] p4: holewidth=2 width=2 viastyle="Through Hole" minholewidth=2 minwidth=2 maxholewidth=2 maxwidth=2
RoutingVias RVS_ThruVia [IsThruVia] p5: holewidth=0.25 width=0.6 viastyle="Through Hole" minholewidth=0.25 minwidth=0.6 maxholewidth=0.25 maxwidth=0.6
SMDEntry SE_All [All] p1: side=TRUE corner=TRUE anyangle=TRUE
ShortCircuit S-C_All [All] p1: allowed=FALSE
SilkToSilkClearance StSC_All [All] p1: silktosilkclearance=0.25
SilkToSolderMaskClearance StSMC_Pad [IsPad] p1: minsilkscreentomaskgap=0.25 clearancetoexposedcopper=TRUE
SolderMaskExpansion SME_MicroVia [IsMicroVia] p1: expansion=0 istentingtop=TRUE soldermaskfromhole=TRUE
SolderMaskExpansion SME_BlindVia [IsBlindVia] p2: expansion=0 istentingtop=TRUE soldermaskfromhole=TRUE
SolderMaskExpansion SME_ThruVia [IsThruVia] p3: expansion=0.075 istentingtop=FALSE soldermaskfromhole=TRUE
SolderMaskExpansion SME_NPTH [(ObjectKind = 'Pad') AND (Layer = 'MultiLayer') AND (PadIsPlated = 'False')] p4: expansion=0.075 istentingtop=FALSE soldermaskfromhole=TRUE
SolderMaskExpansion SME_Check [All] p5 off: expansion=0.05 istentingtop=FALSE
SolderMaskExpansion SME_All [All] p6: expansion=0 istentingtop=FALSE
SupplyNets "Schematic Supply Nets_7" [InNet('VP')] p1: voltage=0.000
SupplyNets "Schematic Supply Nets_6" [InNet('C_VP')] p2: voltage=0.000
SupplyNets "Schematic Supply Nets_5" [InNet('3V3')] p3: voltage=0.000
SupplyNets "Schematic Supply Nets_4" [InNet('C_VDigIO')] p4: voltage=0.000
SupplyNets "Schematic Supply Nets_3" [InNet('5V0_sensor1_2')] p5: voltage=0.000
SupplyNets "Schematic Supply Nets_2" [InNet('5V0')] p6: voltage=0.000
SupplyNets "Schematic Supply Nets_1" [InNet('SGND')] p7: voltage=0.000
SupplyNets "Schematic Supply Nets" [InNet('GND')] p8: voltage=0.000
UnRoutedNet URN_All [All] p1: checkbadconnections=TRUE
UnpouredPolygon MP_All [All] p1:
Width W_onOutside_AND_onMidNexToOutside_uVia [ExistsOnLayer('Top Side') OR ExistsOnLayer('Bottom Side') OR ExistsOnLayer('Mid Layer 1') OR ExistsOnLayer('Mid Layer 6')] p1: maxlimit=4 minlimit=0.15 preferedwidth=0.2 minimp=50.000000 maximp=50.000000 favimp=50.000000 checkconnectedcopper=TRUE
Width W_onMid [ExistsOnLayer('Mid Layer 1') OR ExistsOnLayer('Mid Layer 2') OR ExistsOnLayer('Mid Layer 3') OR ExistsOnLayer('Mid Layer 4') OR ExistsOnLayer('Mid Layer 5') OR ExistsOnLayer('Mid Layer 6') OR ExistsOnLayer('Mid Layer 7') OR ExistsOnLayer('Mid Layer 8') OR ExistsOnLayer('Mid Layer 9') OR ExistsOnLayer('Mid Layer 10')] p2: maxlimit=4 minlimit=0.15 preferedwidth=0.2 minimp=50.000000 maximp=50.000000 favimp=50.000000 checkconnectedcopper=TRUE
11 further rules are at their usual default settings.

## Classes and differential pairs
component class Nano_CAN_RS422: C500 C501 C502 C503 C504 C505 C506 C507 C508 C509 D500 D501 D502 D503 D504 D505 D506 D507 D508 D509 D510 D511 D512 D513 D514 D515 D516 D517 R500 R501 R502 R503 R504 R505 R506 R507 R508 R509 R510 RN500 RN501 RN502 RN503 RN504 TP405 TP406 TP407 TP408 TP411 TP412 TP413 TP414 TP415 TP416 TP418 TP420 TP421 TP422 TP423 TP424 TP425 TP426 TP427 U500 U501
net class NV: U V VP W
net class HV: C_VDigIO C_VP C_W1 C_W2 C_W3 NetC402_1 NetC403_1 NetC404_1

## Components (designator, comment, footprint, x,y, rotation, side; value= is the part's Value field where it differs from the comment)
C200 "0402 100nF" CAPC100X50X70L25N 59.625,40.525 r0 bottom value=100nF
C201 "0402 100nF" CAPC100X50X70L25N 40.75,13.115 r90 bottom locked value=100nF
C202 "0402 100nF" CAPC100X50X70L25N 38,11.75 r0 top value=100nF
C203 "0402 100nF" CAPC100X50X70L25N 53.55,61.625 r90 bottom value=100nF
C204 "C0805C103KBRACAUTO" CAPC200X125X150L47N 6.275,11.6 r270 bottom value=10nF
C205 "C0805C103KBRACAUTO" CAPC200X125X150L47N 61.225,58.475 r90 bottom value=10nF
C206 "0402 100nF" CAPC100X50X70L25N 9.7,57.475 r180 top value=100nF
C207 "0402 100nF" CAPC100X50X70L25N 18.825,61.275 r90 bottom locked value=100nF
C208 "0402 100nF" CAPC100X50X70L25N 17.3,53.55 r90 bottom locked value=100nF
C209 "0402 100nF" CAPC100X50X70L25N 14.45,53.55 r270 bottom locked value=100nF
C210 "0402 100nF" CAPC100X50X70L25N 18.8,56.25 r90 bottom locked value=100nF
C211 "0402 100nF" CAPC100X50X70L25N 15.875,54 r180 bottom locked value=100nF
C212 "0402 100nF" CAPC100X50X70L25N 22.4,61.6 r270 bottom value=100nF
C400 "HHXC500ARA470MHA0G" PANASONIC_F_VIB 7.5,28.8 r180 top value=47µF
C401 "HHXD630ARA220MF80G" PANASONIC_D8_VIB 26.05,40.025 r90 top value=22µF
C402 "0402 470pF" CAPC100X50X70L25N 52.7,40.65 r90 top value=470pF
C403 "0402 470pF" CAPC100X50X70L25N 52.7,30.85 r90 top value=470pF
C404 "0402 470pF" CAPC100X50X70L25N 52.7,21.05 r90 top value=470pF
C405 "0402 220pF" CAPC100X50X70L25N 51.2,40.65 r90 top value=220pF
C406 "0402 220pF" CAPC100X50X70L25N 51.2,30.85 r90 top value=220pF
C407 "0402 220pF" CAPC100X50X70L25N 51.2,21.05 r90 top value=220pF
C408 "1206 4.7uF Soft Termination" CAP320x160x190L60N 28.425,33.325 r90 top value=4.7µF
C409 "1206 4.7uF Soft Termination" CAP320x160x190L60N 26.05,33.325 r90 top value=4.7µF
C410 "1206 4.7uF Soft Termination" CAP320x160x190L60N 23.675,33.325 r90 top value=4.7µF
C411 "1206 4.7uF Soft Termination" CAP320x160x190L60N 34.4,35.225 r180 top value=4.7µF
C412 "1206 4.7uF Soft Termination" CAP320x160x190L60N 17.7,34.8 r0 top value=4.7µF
C413 "0603 1uF" CAPC160X80X100L35N 34,52.05 r90 bottom value=1µF
C414 "0402 100nF" CAPC100X50X70L25N 35.275,52.45 r90 bottom value=100nF
C415 "0402 100nF" CAPC100X50X70L25N 39.325,52.45 r90 bottom value=100nF
C416 "0805 4.7uF" CAPC200X125X150L47N 40.775,51.71 r90 bottom value=4.7µF
C417 "0402 1nF" CAPC100X50X70L25N 38.175,50.7 r90 bottom value=1nF
C418 "0402 22pF" CAPC100X50X70L25N 51.6,13.8 r270 bottom value=22pF
C419 "0402 22pF" CAPC100X50X70L25N 47.8,13.8 r270 bottom value=22pF
C420 "0402 100nF" CAPC100X50X70L25N 49.7,17.7 r270 bottom value=100nF
C421 "0402 100nF" CAPC100X50X70L25N 43.1,64.2 r90 bottom value=100nF
C500 "0402 22pF" CAPC100X50X70L25N 17.35,10.45 r180 bottom value=22pF
C501 "0402 22pF" CAPC100X50X70L25N 19.3,10.45 r0 bottom value=22pF
C502 "0402 100nF" CAPC100X50X70L25N 18.3,5.35 r180 bottom value=100nF
C503 "0402 220pF" CAPC100X50X70L25N 44.45,54.85 r180 bottom value=220pF
C504 "0402 100nF" CAPC100X50X70L25N 44.8,51.35 r90 bottom value=100nF
C505 "0402 220pF" CAPC100X50X70L25N 44.45,57.85 r180 bottom value=220pF
C506 "0402 220pF" CAPC100X50X70L25N 52.15,54.85 r0 bottom value=220pF
C507 "0402 220pF" CAPC100X50X70L25N 52.15,57.85 r0 bottom value=220pF
C508 "0402 220pF" CAPC100X50X70L25N 52.15,49.35 r0 bottom value=220pF
C509 "0402 22pF" CAPC100X50X70L25N 53.25,44.45 r0 bottom value=22pF
D200 "D12V0L1B2LP-7B" DIONPDFN2_102X60X60L25X50N 60.4,46.225 r180 bottom
D201 "1N4148WL2-TP" DIODFN2_102X60X60L25X50N 38.475,13.2 r90 top
D202 "EZAEG2A50AX" DIONPC105X53X43L26N 48.95,12.15 r270 top locked
D203 "EZAEG2A50AX" DIONPC105X53X43L26N 50.45,12.15 r270 top locked
D204 "1N4148WL2-TP" DIODFN2_102X60X60L25X50N 44.575,3.65 r90 bottom locked
D205 "1N4148WL2-TP" DIODFN2_102X60X60L25X50N 42.825,3.65 r90 bottom locked
D206 "SS110LW" SODFL359X170X143L65X95N 41.45,13.975 r0 top locked
D207 "SS110LW" SODFL359X170X143L65X95N 41.45,11.75 r0 top locked
D208 "PESD5V0L4UG" SOT23-5P65_210X110L28X20N 8,52.7 r90 bottom locked
D209 "EZAEG2A50AX" DIONPC105X53X43L26N 45.95,12.15 r270 top
D210 "EZAEG2A50AX" DIONPC105X53X43L26N 47.45,12.15 r270 top
D400 "SMF28A" SODFL359X170X143L65X95N 16,40 r90 top
D401 "1N4148WL2-TP" DIODFN2_102X60X60L25X50N 51.6,15.6 r270 bottom
D402 "1N4148WL2-TP" DIODFN2_102X60X60L25X50N 47.8,15.6 r270 bottom
D403 "PESD5V0L1UL" SODFL_DIODFN2_102X60X60L25X50L 32.3,58 r270 top
D404 "PESD5V0L1UL" SODFL_DIODFN2_102X60X60L25X50L 29.3,58 r270 top
D405 "PTVS3V3D1BALYL" DIONPDFN2_102X60X60L25X50N 36.8,58 r90 top
D406 "PTVS3V3D1BALYL" DIONPDFN2_102X60X60L25X50N 35.3,58 r90 top
D500 "D12V0L1B2LP-7B" DIONPDFN2_102X60X60L25X50N 53.875,53.8 r0 top
D501 "D12V0L1B2LP-7B" DIONPDFN2_102X60X60L25X50N 53.875,51.4 r0 top
D502 "D12V0L1B2LP-7B" DIONPDFN2_102X60X60L25X50N 53.875,48.85 r0 top
D503 "D12V0L1B2LP-7B" DIONPDFN2_102X60X60L25X50N 53.875,45.3 r0 top
D504 "1N4148WL2-TP" DIODFN2_102X60X60L25X50N 25,12.2 r270 bottom
D505 "1N4148WL2-TP" DIODFN2_102X60X60L25X50N 30.1,12.25 r270 bottom
D506 "PTVS3V3D1BALYL" DIONPDFN2_102X60X60L25X50N 25.05,11.05 r90 top
D507 "PTVS3V3D1BALYL" DIONPDFN2_102X60X60L25X50N 30.15,11.05 r90 top
D508 "1N4148WL2-TP" DIODFN2_102X60X60L25X50N 25,10.6 r90 bottom
D509 "1N4148WL2-TP" DIODFN2_102X60X60L25X50N 34,12.2 r270 bottom
D510 "PTVS3V3D1BALYL" DIONPDFN2_102X60X60L25X50N 26.3,11.05 r90 top
D511 "PTVS3V3D1BALYL" DIONPDFN2_102X60X60L25X50N 34.85,6.875 r270 bottom
D512 "1N4148WL2-TP" DIODFN2_102X60X60L25X50N 28.9,10.65 r90 bottom
D513 "1N4148WL2-TP" DIODFN2_102X60X60L25X50N 30.1,10.65 r90 bottom
D514 "PTVS3V3D1BALYL" DIONPDFN2_102X60X60L25X50N 27.6,11.05 r90 top
D515 "PTVS3V3D1BALYL" DIONPDFN2_102X60X60L25X50N 31.4,6.35 r270 bottom
D516 "1N4148WL2-TP" DIODFN2_102X60X60L25X50N 28.9,12.25 r270 bottom
D517 "PTVS3V3D1BALYL" DIONPDFN2_102X60X60L25X50N 28.85,11.05 r90 top
DS200 "598-8010-107F" LEDSC80X160X90L45N_RED 19.3,52.1 r180 top
DS201 "598-8070-107F" LEDSC80X160X90L45N_GREEN 19.3,53.5 r180 top
F400 "0157004." FUSC650X370X403L148N 8.775,37 r0 top
FD200 "FDc80c160" FIDUCIAL_c80_c160 0.9,0.9 r90 top locked
FD201 "FDc80c160" FIDUCIAL_c80_c160 66.1,0.9 r90 bottom locked
FD202 "FDc80c160" FIDUCIAL_c80_c160 66.1,69.1 r90 top locked
FD203 "FDc80c160" FIDUCIAL_c80_c160 0.9,69.1 r90 bottom locked
L400 "SRN8040TA-330M" INDDFN2_800X800X420L232X630N 46,44.8 r0 top value=33µH
L401 "SRN8040TA-330M" INDDFN2_800X800X420L232X630N 46,35 r0 top value=33µH
L402 "SRN8040TA-330M" INDDFN2_800X800X420L232X630N 46,25.2 r0 top value=33µH
LS200 "LAYERSTAIR 8 LAYER" 8LS400X50w/oLETTERS_KEEPOUT 57.075,0.775 r0 top
MH200 "MTGNPH400A900V8H40_Snap-In_Spacer" MTGNPH400A900V8H40_Snap-In_Spacer 5,5 r0 top locked
MH201 "MTGNPH400A900V8H40_Snap-In_Spacer" MTGNPH400A900V8H40_Snap-In_Spacer 62,5 r0 top locked
MH202 "MTGNPH400A900V8H40_Snap-In_Spacer" MTGNPH400A900V8H40_Snap-In_Spacer 62,65 r0 top locked
MH203 "MTGNPH400A900V8H40_Snap-In_Spacer" MTGNPH400A900V8H40_Snap-In_Spacer 5,65 r0 top locked
MH204 "MTGNPH220_NPTH" MTGNPH220 2.5,59 r90 top locked
MH205 "MTGNPH220_NPTH" MTGNPH220 54.525,11.775 r90 top locked
MP200 "973100365" WURTH_973100365 5,5 r225 bottom locked
MP201 "973100365" WURTH_973100365 62,5 r315 bottom locked
MP202 "973100365" WURTH_973100365 62,65 r45 bottom locked
MP203 "973100365" WURTH_973100365 5,65 r135 bottom locked
MP400 "9774015243" WURTH_9774015243_NPTH 17.2,28.95 r90 bottom locked
MP401 "9774015243" WURTH_9774015243_NPTH 28.6,47.35 r90 bottom locked
MP402 "9774015943" WURTH_9774015943_NPTH 23.5,22.65 r90 bottom locked
MP403 "9774015943" WURTH_9774015943_NPTH 34.9,41.05 r90 bottom locked
Q200 "VNS1NV04DP-E" SOIC8P127_490X599X175L83X41N 43.7,8.4 r0 bottom locked
Q400 "CSD17483F4" TRXDFN3_101X61X53L25X15N 41.6,63.6 r0 bottom
R200 "0402 47R" RESC100X52X40L22N 60.075,44.725 r90 bottom value=47
R202 "0402 2.2k" RESC100X52X40L22N 45.6,3.8 r270 bottom locked value=2.2k
R203 "0402 2.2k" RESC100X52X40L22N 41.8,3.8 r270 bottom locked value=2.2k
R204 "0402 220R" RESC100X52X40L22N 45.15,12.575 r0 bottom locked value=220
R205 "0402 220R" RESC100X52X40L22N 42.575,12.575 r0 bottom locked value=220
R206 "1206 2M 500V" RESC320X160X90L47N 4.05,12.2 r270 bottom value=2M
R207 "0402 5.1k" RESC100X52X40L22N 6.25,57.475 r180 top value=5.1k
R208 "0402 5.1k" RESC100X52X40L22N 9.725,50.525 r0 top value=5.1k
R209 "0805 120R" RESC200X125X84L35N 33.1,11.5 r90 top value=120
R210 "0402 0" RESC100X52X40L22N 34.85,4.6 r270 bottom value=0
R211 "0402 680R" RESC100X52X40L22N 19.3,52.1 r180 bottom value=680
R212 "0402 680R" RESC100X52X40L22N 19.3,53.5 r180 bottom value=680
R213 "0402 10k" RESC100X52X40L22N 48.825,44.425 r90 bottom value=10k
R214 "0402 10k" RESC100X52X40L22N 41.6,19.5 r0 bottom value=10k
R215 "0402 10k" RESC100X52X40L22N 41.6,20.525 r0 bottom value=10k
R406 "0603 390R" RESC160X82X65L30N 51.95,38.9 r0 top value=390
R407 "0603 390R" RESC160X82X65L30N 51.95,29.125 r0 top value=390
R408 "0603 390R" RESC160X82X65L30N 51.95,19.3 r0 top value=390
R418 "0402 220R" RESC100X52X40L22N 22.4,59.5 r270 bottom value=220
R421 "0402 0" RESC100X52X40L22N 39.925,53.9 r180 bottom value=0
R422 "0402 470k" RESC100X52X40L22N 35.275,54.375 r90 bottom value=470k
R423 "0402 100k" RESC100X52X40L22N 37.075,55.65 r90 bottom value=100k
R424 "0402 27k" RESC100X52X40L22N 38.1,55.65 r270 bottom value=27k
R425 "0402 16k" RESC100X52X40L22N 36.75,50.7 r90 bottom value=16k
R427 "0402 1M" RESC100X52X40L22N 41.6,64.65 r0 bottom value=1M
R428 "0402 10k" RESC100X52X40L22N 30.6,19.6 r180 bottom value=10k
R429 "0402 0R47" RESC100X52X40L22N 42.225,53.3 r90 bottom value=0.47
R500 "0402 0" RESC100X52X40L22N 16,7.85 r90 bottom value=0
R501 "0402 0" RESC100X52X40L22N 20.6,7.85 r90 bottom value=0
R502 "0402 150R" RESC100X52X40L22N 44.45,55.85 r0 bottom value=150
R503 "0402 150R" RESC100X52X40L22N 44.45,56.85 r0 bottom value=150
R504 "0402 150R" RESC100X52X40L22N 52.15,55.85 r180 bottom value=150
R505 "0402 150R" RESC100X52X40L22N 52.15,56.85 r180 bottom value=150
R506 "0402 150R" RESC100X52X40L22N 52.15,50.35 r180 bottom value=150
R507 "0402 0" RESC100X52X40L22N 46.95,57.85 r180 bottom value=0
R508 "0402 0" RESC100X52X40L22N 48.9,57.85 r0 bottom value=0
R509 "0402 0" RESC100X52X40L22N 49.55,49.35 r0 bottom value=0
R510 "0402 150R" RESC100X52X40L22N 53.25,45.45 r180 bottom value=150
RN400 "TC124-JR-0747KL" RESCAXS8P50_200X102X55L30X30N 49.7,12.3 r0 bottom value=47k
RN500 "4x0402 10k" RESCAXS8P50_200X102X55L30X30N 26.95,11.35 r0 bottom value=10k
RN501 "4x0402 10k" RESCAXS8P50_200X102X55L30X30N 32.05,11.35 r0 bottom value=10k
RN502 "4x0402 4.7k" RESCAXS8P50_200X102X55L30X30N 42.4,56.35 r90 bottom value=4.7k
RN503 "4x0402 4.7k" RESCAXS8P50_200X102X55L30X30N 54.2,56.35 r90 bottom value=4.7k
RN504 "4x0402 4.7k" RESCAXS8P50_200X102X55L30X30N 52.15,52.3 r270 bottom value=4.7k
STEG200 "Steg400X90_7Hole" Steg_400X90_7Hole 16,0 r0 top locked
STEG201 "Steg400X90_7Hole" Steg_400X90_7Hole 51,0 r0 top locked
STEG202 "Steg400X90_7Hole" Steg_400X90_7Hole 67,35 r90 top locked
STEG203 "Steg400X90_7Hole" Steg_400X90_7Hole 51,70 r180 top locked
STEG204 "Steg400X90_7Hole" Steg_400X90_7Hole 16,70 r180 top locked
STEG205 "Steg400X90_7Hole" Steg_400X90_7Hole 0,35 r270 top locked
SW1 "DHN-08F-T-V" SOIC16P127_1139X671X151L61X41N 29.5,5.9 r0 top locked
SYM200 "BARCODE_EMS500x500" BARCODE_EMS_500x500 48.65,35.4 r180 bottom
SYM201 "ESD500X450" ESD_copper_small 15.975,21.4 r0 top
SYM202 "ESD500X450" ESD_copper_small 62.525,53.7 r180 bottom
SYM203 "PCB_MARKING1200x600" MARKING_PCB_1200x600 7.5,22.775 r180 bottom
TP200 "TPc120" TESTPOINT_c120 8.65,48.2 r90 bottom locked
TP201 "TPc120" TESTPOINT_c120 1.2,46.125 r90 bottom locked
TP202 "TPc120" TESTPOINT_c120 60.925,38.95 r0 bottom locked
TP203 "TPc120" TESTPOINT_c120 63.425,38.95 r0 bottom locked
TP204 "TPc120" TESTPOINT_c120 52.05,10.85 r0 bottom locked
TP205 "TPc120" TESTPOINT_c120 48.95,9.4 r0 bottom locked
TP206 "TPc120" TESTPOINT_c120 56.025,41.45 r0 bottom locked
TP207 "TPc120" TESTPOINT_c120 52.3,42.275 r90 bottom locked
TP208 "TPc120" TESTPOINT_c120 53.375,34.425 r90 bottom locked
TP209 "TPc120" TESTPOINT_c120 61.675,25.425 r90 bottom locked
TP211 "TPc120" TESTPOINT_c120 24.425,59.95 r90 bottom locked
TP212 "TPc120" TESTPOINT_c120 20.825,61.175 r90 bottom locked
TP213 "TPc120" TESTPOINT_c120 56.025,45.25 r0 bottom locked
TP214 "TPc120" TESTPOINT_c120 63.7,46.2 r0 bottom locked
TP215 "TPc120" TESTPOINT_c120 58.25,46.45 r0 bottom locked
TP216 "TPc120" TESTPOINT_c120 56.025,49.65 r0 bottom locked
TP217 "TPc120" TESTPOINT_c120 54.425,47.7 r0 bottom locked
TP218 "TPc120" TESTPOINT_c120 56.025,52.15 r0 bottom locked
TP219 "TPc120" TESTPOINT_c120 58.225,50.95 r0 bottom locked
TP220 "TPc120" TESTPOINT_c120 56.375,54.875 r0 bottom locked
TP221 "TPc120" TESTPOINT_c120 55.65,61.225 r270 bottom locked
TP222 "TPc120" TESTPOINT_c120 54.95,64.225 r270 bottom locked
TP223 "TPc120" TESTPOINT_c120 37.2,14.85 r90 bottom locked
TP224 "TPc120" TESTPOINT_c120 47.5,6 r90 bottom locked
TP225 "TPc120" TESTPOINT_c120 39.9,6 r90 bottom locked
TP226 "TPc120" TESTPOINT_c120 40,11.1 r90 bottom locked
TP227 "TPc120" TESTPOINT_c120 32.15,50.55 r0 bottom locked
TP228 "TPc120" TESTPOINT_c120 52.25,63.675 r270 bottom locked
TP229 "TPc120" TESTPOINT_c120 38.625,8.375 r90 bottom locked
TP230 "TPc120" TESTPOINT_c120 29.3,60.3 r90 bottom locked
TP232 "TPc120" TESTPOINT_c120 32.3,60.3 r90 bottom locked
TP234 "TPc120" TESTPOINT_c120 35.1,60.2 r90 bottom locked
TP235 "TPc120" TESTPOINT_c120 43.95,30.575 r90 bottom locked
TP236 "TPc120" TESTPOINT_c120 39.9,15.55 r90 bottom locked
TP237 "TPc120" TESTPOINT_c120 37.7,60.2 r90 bottom locked
TP238 "TPc120" TESTPOINT_c120 30.75,56.625 r90 bottom locked
TP239 "TPc120" TESTPOINT_c120 23.8,7.65 r90 bottom locked
TP240 "TPc120" TESTPOINT_c120 10.1,14 r90 bottom locked
TP241 "TPc120" TESTPOINT_c120 10.1,16.6 r90 bottom locked
TP242 "TPc120" TESTPOINT_c120 12.875,15.25 r90 bottom locked
TP243 "TPc120" TESTPOINT_c120 26.35,9 r90 bottom locked
TP244 "TPc120" TESTPOINT_c120 65.7,20.7 r180 bottom locked
TP245 "TPc120" TESTPOINT_c120 27.275,6.375 r90 bottom locked
TP246 "TPc120" TESTPOINT_c120 4.175,55.35 r0 bottom locked
TP247 "TPc120" TESTPOINT_c120 9.9,57.7 r0 bottom locked
TP248 "TPc120" TESTPOINT_c120 28.85,8.75 r90 bottom locked
TP249 "TPc120" TESTPOINT_c120 6.7,57.8 r0 bottom locked
TP250 "TPc120" TESTPOINT_c120 29.775,6.375 r90 bottom locked
TP251 "TPc120" TESTPOINT_c120 12.475,51.075 r0 bottom locked
TP252 "TPc120" TESTPOINT_c120 12.475,48.575 r0 bottom locked
TP253 "TPc120" TESTPOINT_c120 31.4,9 r90 bottom locked
TP254 "TPc120" TESTPOINT_c120 8.9,55.2 r0 bottom locked
TP255 "TPc120" TESTPOINT_c120 33.025,6.375 r90 bottom locked
TP256 "TPc120" TESTPOINT_c120 36.05,2.85 r90 bottom locked
TP257 "TPc120" TESTPOINT_c120 33.95,9 r90 bottom locked
TP258 "TPc120" TESTPOINT_c120 21.45,52.1 r90 bottom locked
TP259 "TPc120" TESTPOINT_c120 43.075,61.75 r270 bottom locked
TP260 "TPc120" TESTPOINT_c120 42.075,66.55 r270 bottom locked
TP261 "TPc120" TESTPOINT_c120 28.55,53.4 r90 bottom locked
TP262 "TPc120" TESTPOINT_c120 14.7,63.5 r90 bottom locked
TP263 "TPc120" TESTPOINT_c120 17.7,63.5 r90 bottom locked
TP264 "TPc120" TESTPOINT_c120 16.2,65.625 r90 bottom locked
TP265 "TPc120" TESTPOINT_c120 53.125,68.025 r270 bottom locked
TP266 "TPc120" TESTPOINT_c120 51.2,21.2 r180 bottom locked
TP267 "TPc120" TESTPOINT_c120 49,20 r180 bottom locked
TP268 "TPc120" TESTPOINT_c120 49.2,24 r180 bottom locked
TP269 "TPc120" TESTPOINT_c120 46.5,31 r180 bottom locked
TP270 "TPc120" TESTPOINT_c120 17.8,21.9 r180 bottom locked
TP400 "TPc120" TESTPOINT_c120 41.8,48.5 r90 bottom locked
TP401 "TPc120" TESTPOINT_c120 41.925,38.55 r90 bottom locked
TP402 "TPc120" TESTPOINT_c120 40.375,25.3 r90 bottom locked
TP403 "TPc120" TESTPOINT_c120 30.825,24.525 r90 bottom locked
TP404 "TPc120" TESTPOINT_c120 65.7,17.7 r90 bottom locked
TP405 "TPc120" TESTPOINT_c120 23.325,11.85 r0 bottom locked
TP406 "TPc120" TESTPOINT_c120 31.275,14.2 r0 bottom locked
TP407 "TPc120" TESTPOINT_c120 20.825,5.3 r0 bottom locked
TP408 "TPc120" TESTPOINT_c120 25.31,14.099 r0 bottom locked
TP409 "TPc120" TESTPOINT_c120 11.4,34.775 r90 bottom locked
TP410 "TPc120" TESTPOINT_c120 20.225,32 r90 bottom locked
TP411 "TPc120" TESTPOINT_c120 43.925,33.25 r0 bottom locked
TP412 "TPc120" TESTPOINT_c120 15.775,5.3 r0 bottom locked
TP413 "TPc120" TESTPOINT_c120 14.75,17.775 r0 bottom locked
TP414 "TPc120" TESTPOINT_c120 16.7,19.625 r0 bottom locked
TP415 "TPc120" TESTPOINT_c120 7.45,37.9 r0 bottom locked
TP416 "TPc120" TESTPOINT_c120 45.5,59.425 r0 bottom locked
TP417 "TPc120" TESTPOINT_c120 32.175,53.45 r180 bottom locked
TP418 "TPc120" TESTPOINT_c120 48.425,59.425 r0 bottom locked
TP419 "TPc120" TESTPOINT_c120 30.15,21.5 r0 bottom locked
TP420 "TPc120" TESTPOINT_c120 46.85,48.625 r0 bottom locked
TP421 "TPc120" TESTPOINT_c120 51.175,45 r0 bottom locked
TP422 "TPc120" TESTPOINT_c120 43.785,53.25 r0 bottom locked
TP423 "TPc120" TESTPOINT_c120 41.975,58.775 r0 bottom locked
TP424 "TPc120" TESTPOINT_c120 50.95,59.4 r0 bottom locked
TP425 "TPc120" TESTPOINT_c120 54.2,58.9 r0 bottom locked
TP426 "TPc120" TESTPOINT_c120 49.325,47.775 r0 bottom locked
TP427 "TPc120" TESTPOINT_c120 51.825,47.775 r0 bottom locked
TP428 "TPc120" TESTPOINT_c120 22.4,57.45 r0 bottom locked
TP430 "TPc120" TESTPOINT_c120 51.6,17.45 r0 bottom locked
TP431 "TPc120" TESTPOINT_c120 45.9,28.525 r0 bottom locked
TP432 "TPc120" TESTPOINT_c120 39.5,64.65 r0 bottom locked
TP433 "TPc120" TESTPOINT_c120 49.025,29.875 r0 bottom locked
TP434 "TPc120" TESTPOINT_c120 54.1,39.575 r0 bottom locked
TP435 "TPc120" TESTPOINT_c120 53.4,31.825 r0 bottom locked
TP436 "TPc120" TESTPOINT_c120 53.625,20.4 r0 bottom locked
TP437 "TPc120" TESTPOINT_c120 39.875,55.6 r180 bottom locked
TP438 "TPc120" TESTPOINT_c120 35.125,49.6 r180 bottom locked
TP439 "TPc120" TESTPOINT_c120 53.225,14.25 r0 bottom locked
TP440 "TPc120" TESTPOINT_c120 47.5,17.45 r0 bottom locked
U200 "SN74LVC1G17DCK" SOT23-5P65_210X110L28X20N 59.15,42.4 r90 bottom
U201 "SN74AHCT1G00DCKR" SOT23-5P65_210X110L28X20N 45.05,15.09 r0 bottom locked
U202 "SN74AHCT1G00DCKR" SOT23-5P65_210X110L28X20N 42.35,15.09 r0 bottom locked
U203 "MAX202IPW" SOP16P65_500X640X120L83X24N 15.55,58.2 r180 bottom locked
U400 "TPS259470ARPWR" QFN16P45_200X200X100L15X25N 37.3,53.175 r0 bottom
U401 "SN74LVC2G17DCKR" SOT23-6P65_210X110L27X20N 49.7,15.15 r180 bottom
U500 "TJA1051TK/3/1J" SON9P65_300X300X100L40X30T240X160N 18.3,7.85 r180 bottom
U501 "AM26LV32EIPWR" SOP16P65_500X640X120L83X24N 48.25,53.6 r0 bottom
X1 "39281023" MOLEX_460150202 8,44 r270 top locked
X3 "39281043" MOLEX_460150402 59.6,31.45 r90 top locked
X4 "430450612" "MOLEX_ 430450612" 61,17.7 r270 top locked
X5 "52601-S10-8LF" AMPHENOL_52601-S10-8LF 60.025,48.75 r90 top locked
X7 "5025840860" MOLEX_5025840860 45.2,5.4 r180 top locked
X8 "5025840760" MOLEX_5025840760 33.8,64.6 r0 top locked
X10 "RS232" MOLEX_5025840560 17.7,64.6 r0 top locked
X11 "5025840460" MOLEX_5025840460 5.4,16.8 r90 top locked
X12 "5025840460" MOLEX_5025840460 16.8,5.4 r180 top locked
X13 "USB4115-03-C" GTC_USB4115-03-C 8,54 r0 top locked
X16 "430450212" "MOLEX_ 430450212" 47.6,64.35 r0 top locked
X200 "AXT410124" PANASONIC_AXT410124 54.55,65.275 r180 top locked
X400a "AXF5G6012" PANASONIC_AXF5G6012 17.7,40.5 r90 bottom locked
X400b "AXF5G6012" PANASONIC_AXF5G6012 34.4,29.5 r270 bottom locked

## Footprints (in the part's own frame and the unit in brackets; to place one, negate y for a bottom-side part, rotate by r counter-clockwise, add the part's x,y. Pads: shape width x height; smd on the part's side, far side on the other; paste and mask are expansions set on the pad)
8LS400X50w/oLETTERS_KEEPOUT [mm] "Layerstair 8 Layers, 4.00 mm X 0.5 mm, without Letters and KeepOut"
  Top Side region: -2,-0.25 -1.5,-0.25 -1.5,0.25 -2,0.25
  Mid Layer 1 region: -1.5,-0.25 -1,-0.25 -1,0.25 -1.5,0.25
  Mid Layer 2 region: -1,-0.25 -0.5,-0.25 -0.5,0.25 -1,0.25
  Mid Layer 6 region: 1.5,0.25 1,0.25 1,-0.25 1.5,-0.25
  Mid Layer 5 region: 1,0.25 0.5,0.25 0.5,-0.25 1,-0.25
  Bottom Side region: 1.5,-0.25 2,-0.25 2,0.25 1.5,0.25
AMPHENOL_52601-S10-8LF [mm] "Header, 2.54mm Pitch, Dual Row, SMT, Vertical, 10 Circuits"
  rrect50% 1.27x3.18 smd: 1(-5.08,-2.73) 2(-5.08,2.73) 3(-2.54,-2.73) 4(-2.54,2.73) 5(0,-2.73) 6(0,2.73) 7(2.54,-2.73) 8(2.54,2.73) 9(5.08,-2.73) 10(5.08,2.73)
  body extent -10.05,-4.38 10.05,4.38, height 12.76
BARCODE_EMS_500x500 [mm] "Barcode EMS, 5.00 mm L X 5.00 mm W X 0.00 mm H body"
  Top Side keep-out region: -2.5,2.5 2.5,2.5 2.5,-2.5 -2.5,-2.5
  body extent -2.5,-2.5 2.5,2.5, height 0.01
CAP320x160x190L60N [mm] "Capacitor, Chip; 3.20 mm L X 1.60 mm W X 1.90 mm H body"
  rrect35% 1.428x1.91 smd: 1(-1.391,0) 2(1.391,0)
  body extent -1.75,-0.95 1.75,0.95, height 1.9
CAPC100X50X70L25N [mm] "Capacitor, Chip; 1.00 mm L X 0.50 mm W X 0.70 mm H body"
  rrect49% 0.63x0.61 smd: 1(-0.45,0) 2(0.45,0)
  body extent -0.55,-0.3 0.55,0.3, height 0.7
CAPC160X80X100L35N [mm] "Capacitor, Chip; 1.60 mm L X 0.80 mm W X 1.00 mm H body"
  rrect50% 0.96x1.02 smd: 1(-0.725,0) 2(0.725,0)
  body extent -0.9,-0.5 0.9,0.5, height 1
CAPC200X125X150L47N [mm] "Capacitor, Chip; 2.00 mm L X 1.25 mm W X 1.50 mm H body"
  rrect42% 1.18x1.47 smd: 1(-0.865,0) 2(0.865,0)
  body extent -1.15,-0.72 1.15,0.72, height 1.5
DIODFN2_102X60X60L25X50N [mm] "Diode, Dual Flat No-Lead (DFN 2 Pin); 2 pin, 1.025 mm L X 0.60 mm W X 0.60 mm H body"
  rect 0.36x0.63 smd: 1(-0.325,0) 2(0.325,0)
  body extent -0.55,-0.35 0.55,0.35, height 0.6
DIONPC105X53X43L26N [mm] "Diode, Non-polarized, Chip; 1.05 mm L X 0.53 mm W X 0.43 mm H Body"
  rrect50% 0.65x0.625 smd: 1(-0.485,0) 2(0.485,0)
  body extent -0.6,-0.3 0.6,0.31, height 0.43
DIONPDFN2_102X60X60L25X50N [mm] "Diode, Non-polarized, Dual Flat No-Lead, 2 pin; 1.025 mm L X 0.60 mm W X 0.60 mm H body"
  rect 0.28x0.549 smd: 1(-0.325,0) 2(0.325,0)
  body extent -0.55,-0.35 0.55,0.35, height 0.6
ESD_copper_small [mm] "ESD-Sign copper 5.0x4.5mm"
  Top Side region: 1157 vertices and 0 holes, not listed, extent -1.517,-1.207 1.291,0.001
  Top Side region: 575 vertices and 0 holes, not listed, extent 0.39,-0.947 1.392,0.012
  Top Side region: 602 vertices and 0 holes, not listed, extent -0.696,0.176 0.501,1.443
  Top Side lines w0.3: -2.242,-1.599 0.003,2.289 2.247,-1.599 -2.242,-1.599
FIDUCIAL_c80_c160 [mm] "Fiducial, Global; 0 pin"
  round 0.8 smd paste-0.8 mask+0.4: 1(0,0)
  Top Side keep-out circle w0.025: c0,0 r0.8
FUSC650X370X403L148N [mm] "Fuse, Chip; 6.50 mm L X 3.70 mm W X 4.03 mm H body"
  rrect21% 2.4x3 smd: 1(-2.43,0) 2(2.43,0)
  body extent -3.35,-1.91 3.35,1.91, height 4.03
GTC_USB4115-03-C [mm] "USB Type C, SHLD, 24poles"
  round 0.66 hole 0.66 unplated mask+0.15: 0(-3.75,0)
  round 0.58 hole 0.58 unplated mask+0.15: 0(3.75,0)
  rect 0.3x0.79 smd: A1(-2.75,0.805) A2(-2.25,0.805) A11(2.25,0.805) A12(2.75,0.805) B1(2.75,-0.805) B2(2.25,-0.805) B11(-2.25,-0.805) B12(-2.75,-0.805)
  rect 0.3x0.85 smd: A3(-1.75,0.835) A4(-1.25,0.835) A5(-0.75,0.835) A6(-0.25,0.835) A7(0.25,0.835) A8(0.75,0.835) A9(1.25,0.835) A10(1.75,0.835) B3(1.75,-0.835) B4(1.25,-0.835) B5(0.75,-0.835) B6(0.25,-0.835) B7(-0.25,-0.835) B8(-0.75,-0.835) B9(-1.25,-0.835) B10(-1.75,-0.835)
  round 1.1 hole 0.7: S1(-2.4,2.15) S2(-2.4,-2.15) S3(2.4,-2.15) S4(2.4,2.15)
  Top Side keep-out region: 0.8,-2.5 -0.8,-2.5 -0.8,-1.8 0.8,-1.8
  Top Side keep-out region: 0.8,1.8 -0.8,1.8 -0.8,2.5 0.8,2.5
  body extent -4.47,-2.3 4.47,2.3, height 9.25
INDDFN2_800X800X420L232X630N [mm] "Inductor, Dual Flat No-Lead, 2 pin; 8.00 mm L X 8.00 mm W X 4.20 mm H Body"
  rect 2.911x8.1 smd: 1(-2.775,0) 2(2.775,0)
  body extent -4.15,-4.15 4.15,4.15, height 4.2
LEDSC80X160X90L45N_GREEN [mm] "LED, Side Concave Package; 2 pin, 0.80 mm L X 1.60 mm W X 0.90 mm H body, green"
  rrect50% 0.94x0.749 smd: 1(-0.745,0) 2(0.745,0)
  body extent -0.85,-0.45 0.85,0.45, height 0.9
LEDSC80X160X90L45N_RED [mm] "LED, Side Concave Package; 2 pin, 0.80 mm L X 1.60 mm W X 0.90 mm H body, red"
  rrect50% 0.94x0.749 smd: 1(-0.745,0) 2(0.745,0)
  body extent -0.85,-0.45 0.85,0.45, height 0.9
MARKING_PCB_1200x600 [mm] "Marking PCB, 12.00 mm L X 6.00 mm W X 0.00 mm H body"
  Top Side keep-out region: -6,3 6,3 6,-3 -6,-3
  body extent -6,-3 6,3, height 0.02
MOLEX_460150202 [mm] "Header, Vertical Shrouded, 4.20 mm row X 5.50 mm column pitch; 1.00 mm lead width, 2 pins, 2 rows, 1 pin per row, 5.40 mm L X 9.60 mm W X 12.80 mm H body"
  rrect50% 2.33x2.33 hole 1.4: 1(0,2.75)
  round 2.33 hole 1.4: 2(0,-2.75)
  body extent -3.1,-6 3.1,5, height 12.81
MOLEX_460150402 [mm] "Header, Vertical Shrouded, 4.20 mm row X 5.50 mm column pitch; 1.00 mm lead width, 4 pins, 2 rows, 2 pins per row, 9.60 mm L X 9.60 mm W X 12.80 mm H body"
  rrect50% 2.33x2.33 hole 1.4: 1(-2.1,2.55)
  round 2.33 hole 1.4: 2(2.1,2.55) 3(-2.1,-2.95) 4(2.1,-2.95)
  body extent -5.2,-6.2 5.2,4.8, height 12.8
MOLEX_5025840460 [mm] "Header, 1.5mm pitch, 4 position, top entry, SMT"
  rrect50% 1.8x3.3 smd: 0(-4.85,1.275) 0(4.85,1.275)
  rrect50% 0.8x2.4 smd: 1(-2.25,-3.775) 2(-0.75,-3.775) 3(0.75,-3.775) 4(2.25,-3.775)
  Top Side keep-out region: 1.9,1.379 3.9,1.379 3.9,3.429 1.9,3.429
  Top Side keep-out region: 5.55,-1.425 2.725,-1.425 2.725,-4.025 5.55,-4.025
  Top Side keep-out region: 1.225,-4.024 1.775,-4.024 1.775,-1.424 1.225,-1.424
  Top Side keep-out region: -0.275,-4.024 0.275,-4.024 0.275,-1.424 -0.275,-1.424
  Top Side keep-out region: -1.775,-4.024 -1.225,-4.024 -1.225,-1.424 -1.775,-1.424
  Top Side keep-out region: -1.9,3.429 -3.9,3.429 -3.9,1.379 -1.9,1.379
  Top Side keep-out region: -0.91,0.869 0.91,0.869 0.91,3.429 -0.91,3.429
  Top Side keep-out region: -5.55,-4.024 -2.725,-4.024 -2.725,-1.424 -5.55,-1.424
  Top Side keep-out lines w0.05: -2.7,-1.449 2.7,-1.449
  body extent -5.15,-4.22 5.15,3.18, height 7.3
MOLEX_5025840560 [mm] "Header, 1.50mm Pitch, Receptacle, Single Row, SMT, Vertical, 5 Circuits"
  rrect50% 1.8x3.3 smd: 0(-5.6,1.275) 0(5.6,1.275)
  rrect50% 0.8x2.4 smd: 1(-3,-3.775) 2(-1.5,-3.775) 3(0,-3.775) 4(1.5,-3.775) 5(3,-3.775)
  Top Side keep-out region: 1.95,-4.024 2.55,-4.024 2.55,-1.424 1.95,-1.424
  Top Side keep-out region: 0.45,-4.024 1.05,-4.024 1.05,-1.424 0.45,-1.424
  Top Side keep-out region: -1.05,-4.024 -0.45,-4.024 -0.45,-1.424 -1.05,-1.424
  Top Side keep-out region: 2.65,1.379 4.65,1.379 4.65,3.429 2.65,3.429
  Top Side keep-out region: 6.3,-1.425 3.45,-1.425 3.45,-4.025 6.3,-4.025
  Top Side keep-out region: -2.65,3.429 -4.65,3.429 -4.65,1.379 -2.65,1.379
  Top Side keep-out region: -2.55,-4.024 -1.95,-4.024 -1.95,-1.424 -2.55,-1.424
  Top Side keep-out region: -6.3,-4.024 -3.45,-4.024 -3.45,-1.424 -6.3,-1.424
  Top Side keep-out region: -0.91,0.869 0.91,0.869 0.91,3.429 -0.91,3.429
  Top Side keep-out lines w0.05: -3.45,-1.449 3.45,-1.449
  body extent -5.9,-4.22 5.9,3.18, height 7.3
MOLEX_5025840760 [mm] "Connector, 1.50mm Pitch, Receptacle, Single Row, SMT, Vertical, 7 Circuits"
  rrect50% 1.8x3.3 smd: 0(-7.1,1.275) 0(7.1,1.275)
  rrect50% 0.8x2.4 smd: 1(-4.5,-3.775) 2(-3,-3.775) 3(-1.5,-3.775) 4(0,-3.775) 5(1.5,-3.775) 6(3,-3.775) 7(4.5,-3.775)
  Top Side keep-out region: -0.91,0.869 0.91,0.869 0.91,3.429 -0.91,3.429
  Top Side keep-out region: -7.8,-4.024 -4.95,-4.024 -4.95,-1.424 -7.8,-1.424
  Top Side keep-out region: -4.05,-4.024 -3.45,-4.024 -3.45,-1.424 -4.05,-1.424
  Top Side keep-out region: -4.15,3.428 -6.15,3.428 -6.15,1.378 -4.15,1.378
  Top Side keep-out region: -2.55,-4.024 -1.95,-4.024 -1.95,-1.424 -2.55,-1.424
  Top Side keep-out region: -1.05,-4.024 -0.45,-4.024 -0.45,-1.424 -1.05,-1.424
  Top Side keep-out region: 0.45,-4.024 1.05,-4.024 1.05,-1.424 0.45,-1.424
  Top Side keep-out region: 1.95,-4.024 2.55,-4.024 2.55,-1.424 1.95,-1.424
  Top Side keep-out region: 3.45,-4.024 4.05,-4.024 4.05,-1.424 3.45,-1.424
  Top Side keep-out region: 7.8,-1.424 4.95,-1.424 4.95,-4.024 7.8,-4.024
  Top Side keep-out region: 4.149,1.378 6.149,1.378 6.149,3.428 4.149,3.428
  Top Side keep-out lines w0.05: -4.95,-1.449 4.95,-1.449
  body extent -7.4,-4.22 7.4,3.18, height 7.3
MOLEX_5025840860 [mm] "Connector, 1.50mm Pitch, Receptacle, Single Row, SMT, Vertical, 8 Pins"
  rrect50% 1.8x3.3 smd: 0(-7.85,1.275) 0(7.85,1.275)
  rrect50% 0.8x2.4 smd: 1(-5.25,-3.775) 2(-3.75,-3.775) 3(-2.25,-3.775) 4(-0.75,-3.775) 5(0.75,-3.775) 6(2.25,-3.775) 7(3.75,-3.775) 8(5.25,-3.775)
  Top Side keep-out region: -0.91,0.869 0.91,0.869 0.91,3.429 -0.91,3.429
  Top Side keep-out region: -4.9,3.429 -6.9,3.429 -6.9,1.379 -4.9,1.379
  Top Side keep-out region: -4.8,-4.024 -4.2,-4.024 -4.2,-1.424 -4.8,-1.424
  Top Side keep-out region: -8.55,-4.024 -5.7,-4.024 -5.7,-1.424 -8.55,-1.424
  Top Side keep-out region: -3.3,-4.024 -2.7,-4.024 -2.7,-1.424 -3.3,-1.424
  Top Side keep-out region: -1.8,-4.024 -1.2,-4.024 -1.2,-1.424 -1.8,-1.424
  Top Side keep-out region: -0.3,-4.024 0.3,-4.024 0.3,-1.424 -0.3,-1.424
  Top Side keep-out region: 1.2,-4.024 1.8,-4.024 1.8,-1.424 1.2,-1.424
  Top Side keep-out region: 2.7,-4.024 3.3,-4.024 3.3,-1.424 2.7,-1.424
  Top Side keep-out region: 4.2,-4.024 4.8,-4.024 4.8,-1.424 4.2,-1.424
  Top Side keep-out region: 4.9,1.379 6.9,1.379 6.9,3.429 4.9,3.429
  Top Side keep-out region: 8.55,-1.425 5.7,-1.425 5.7,-4.025 8.55,-4.025
  Top Side keep-out lines w0.05: 5.7,-1.449 -5.7,-1.449
  body extent -8.15,-4.22 8.15,3.18, height 7.3
"MOLEX_ 430450212" [mm] "Micro-Fit 3.0 Vertical Header, 3.00mm Pitch, Dual Row, 2 Circuits, with PCB Polarizing Peg, Black"
  round 0 hole 1.1 unplated mask+0.15: 0(-3,2.44) 0(3,2.44)
  rrect50% 1.8x1.8 hole 1.1: 1(0,-1.5)
  round 1.8 hole 1.1: 2(0,1.5)
  body extent -3.57,-3.94 3.57,4.83, height 9.95
"MOLEX_ 430450612" [mm] "Micro-Fit 3.0 Vertical Header, 3.00mm Pitch, Dual Row, 6 Circuits, with PCB Polarizing Peg, Black"
  round 0 hole 1.1 unplated mask+0.15: 0(-6,2.44) 0(6,2.44)
  rrect50% 1.8x1.8 hole 1.1: 1(3,-1.5)
  round 1.8 hole 1.1: 2(0,-1.5) 3(-3,-1.5) 4(3,1.5) 5(0,1.5) 6(-3,1.5)
  body extent -6.58,-3.97 6.58,4.8, height 9.95
MTGNPH220 [mm] "Mounting Hole, Non-Plated; 0.00 mm Clearance, 2.20 mm Hole"
  round 0 hole 2.2 unplated paste-2539.97 mask+0.15: 1(0,0)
